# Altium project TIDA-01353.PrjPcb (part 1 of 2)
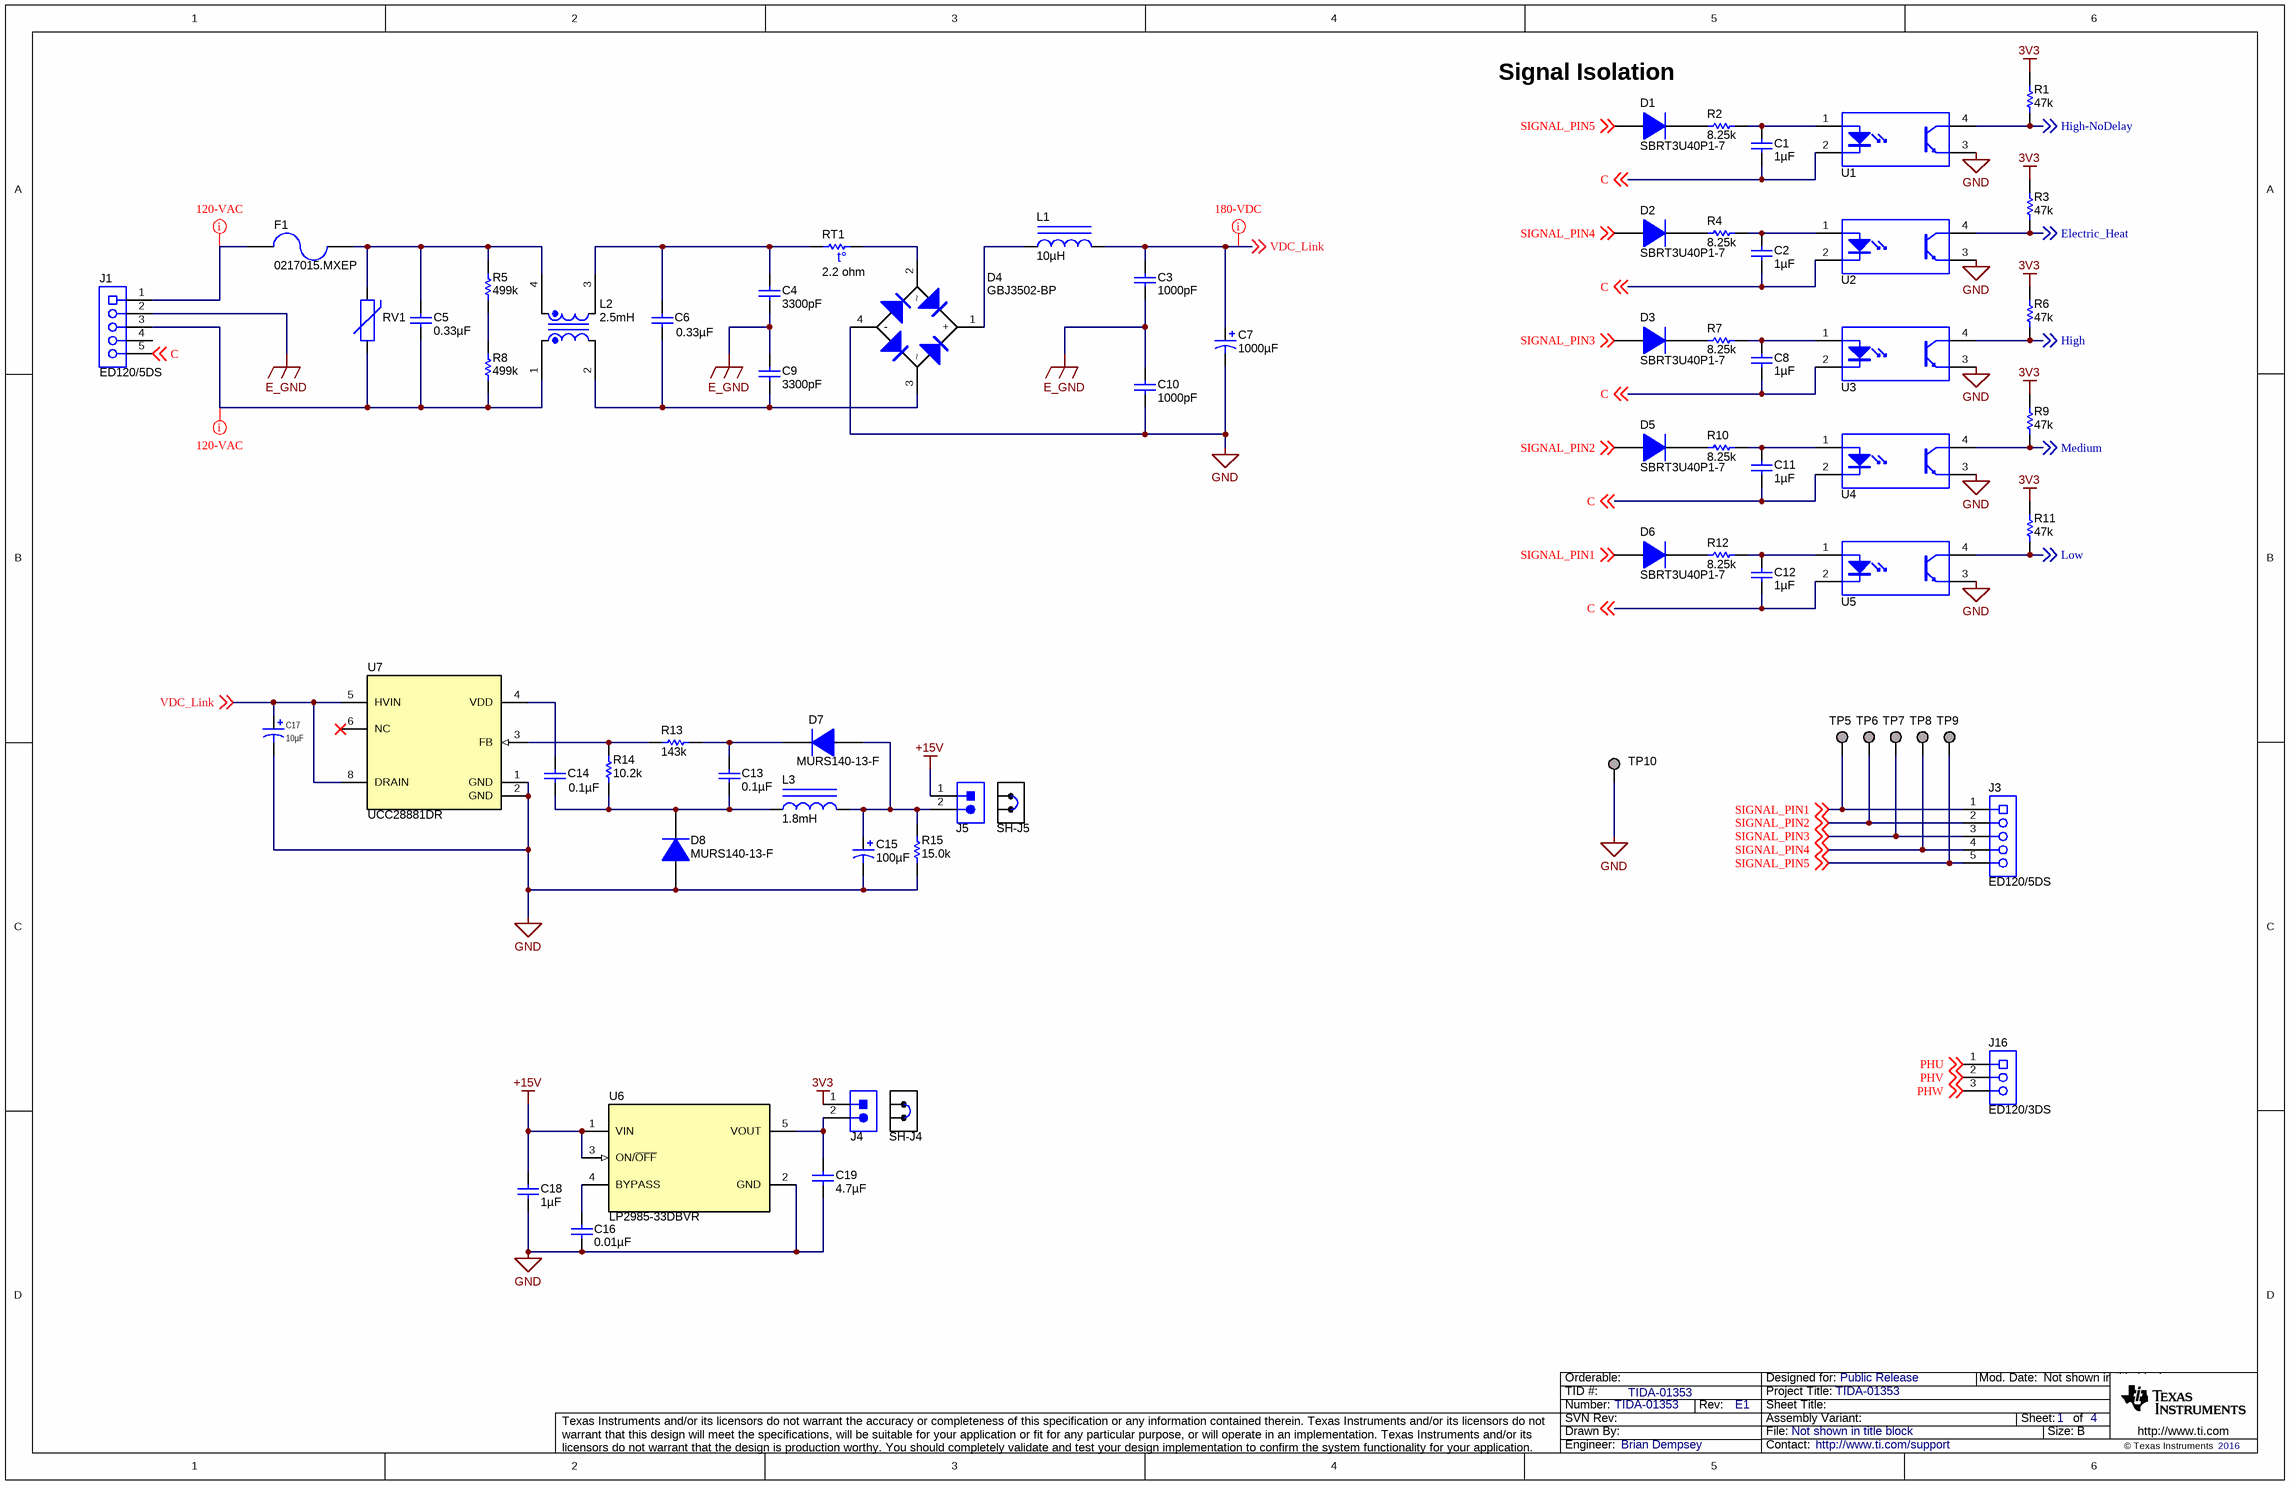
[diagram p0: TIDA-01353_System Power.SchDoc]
TID: TIDA-01353; TechSupport: http://www.ti.com/support; SCH_Rev: E1; PRJ_Title: TIDA-01353; PRJ_Number: TIDA-01353; PRJ_Engineer: Brian Dempsey; PRJ_Customer: Public Release; PCB_Rev: E1; PCB_Layout: Krypton Solutions/RS; CopyrightYear: 2016
4 sheets, 251 parts. Net scope: global (net labels, ports and power ports of the same name join across sheets).
Board file: TIDA-01353.PcbDoc
Sheets:
  TIDA-01353_System Power.SchDoc
  TIDA-01353_Motor Control.SchDoc
  TIDA-01353_MCU and Peripherals.SchDoc
  TIDA-01353_EVM_Hardware.SchDoc

## Sheet TIDA-01353_System Power.SchDoc
size 431 x 279 mm; Date: Not shown in title block; ApprovedBy: Not shown in title block; CheckedBy: Not shown in title block; Author: Not shown in title block; CompanyName: Not shown in title block; Engineer: Not shown in title block; Organization: Not shown in title block; Address1: Not shown in title block; Address2: Not shown in title block; Address3: Not shown in title block; Address4: Not shown in title block; DocumentNumber: 1; Revision: Use project parameter SCH_Rev; SheetNumber: 1; SheetTotal: 4; PageSetup: Record=PageOptions¦CenterHorizontal=True¦CenterVertical=True¦PrintScale=0.62¦XCorrection=1.00¦YCorrection=1.00¦PrintKind=0¦BorderSize=5000000¦LeftOffset=0¦BottomOffset=0¦Orientation=2¦PaperLength=1000¦PaperWidth=1000¦Scale=100¦PaperSource=15¦PrintQuality=600¦MediaType=1¦DitherType=10¦PrintScaleMode=1¦PaperKind=Letter

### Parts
C1  ValueDisplayed: 1µF  [0805_HV]  (hidden comment: 08055C105KAT2A)
C2  ValueDisplayed: 1µF  [0805_HV]  (hidden comment: 08055C105KAT2A)
C3  ValueDisplayed: 1000pF  [CAPRD750W60D750H1050]  (hidden comment: VY2102M29Y5UG63V7)
C4  ValueDisplayed: 3300pF  [KX_1000x700]  (hidden comment: DE1E3KX332MN4AP01F)
C5  ValueDisplayed: 0.33µF  [CAPRR1500W80D1750T1000H1650]  (hidden comment: BFC233840334)
C6  ValueDisplayed: 0.33µF  [CAPRR1500W80D1750T1000H1650]  (hidden comment: BFC233840334)
C7  ValueDisplayed: 1000µF  [381LR_3000x3500]  (hidden comment: 381LR102M200K032)
C8  ValueDisplayed: 1µF  [0805_HV]  (hidden comment: 08055C105KAT2A)
C9  ValueDisplayed: 3300pF  [KX_1000x700]  (hidden comment: DE1E3KX332MN4AP01F)
C10  ValueDisplayed: 1000pF  [CAPRD750W60D750H1050]  (hidden comment: VY2102M29Y5UG63V7)
C11  ValueDisplayed: 1µF  [0805_HV]  (hidden comment: 08055C105KAT2A)
C12  ValueDisplayed: 1µF  [0805_HV]  (hidden comment: 08055C105KAT2A)
C13  ValueDisplayed: 0.1µF  [0603]  (hidden comment: C0603C104K5RACTU)
C14  ValueDisplayed: 0.1µF  [0402]  (hidden comment: GRM155R61A104KA01D)
C15  ValueDisplayed: 100µF  [SM_RADIAL_D8]  (hidden comment: EEE-FK1V101XP)
C16  ValueDisplayed: 0.01µF  [0805_HV]  (hidden comment: C0805C103K5RACTU)
C17  ValueDisplayed: 10µF  [CY_1000x1600]  (hidden comment: UCY2G100MPD1TD)
C18  ValueDisplayed: 1µF  [0603]  (hidden comment: GRM188R61E105KA12D)
C19  ValueDisplayed: 4.7µF  [0603]  (hidden comment: GRM188R60J475KE19D)
D1  SBRT3U40P1-7  [PowerDI123]
D2  SBRT3U40P1-7  [PowerDI123]
D3  SBRT3U40P1-7  [PowerDI123]
D4  GBJ3502-BP  [GBJ]
D5  SBRT3U40P1-7  [PowerDI123]
D6  SBRT3U40P1-7  [PowerDI123]
D7  MURS140-13-F  [SMB]
D8  MURS140-13-F  [SMB]
F1  0217015.MXEP  [Fuse_217_015]
J1  ED120/5DS  [On-Shore_ED120_5DS]
J3  ED120/5DS  [On-Shore_ED120_5DS]
J4  HTSW-102-09-G-S  [Samtec_HTSW-102-09-x-S]  (value not drawn)
J5  HTSW-102-09-G-S  [Samtec_HTSW-102-09-x-S]  (value not drawn)
J16  ED120/3DS  [On-Shore_ED120_3DS]
L1  ValueDisplayed: 10µH  [XAL1010]  (hidden comment: XAL1010-103MEB)
L2  ValueDisplayed: 2.5mH  [8100_8109-8114]  (hidden comment: 8114-RC)
L3  ValueDisplayed: 1.8mH  [MSS1210]  (hidden comment: MSS1210-185KE)
R1  value 47k  [0603]  (hidden comment: CRCW060347K0JNEA)
R2  ValueDisplayed: 8.25k  [2512]  (hidden comment: CRCW25128K25FKEG)
R3  value 47k  [0603]  (hidden comment: CRCW060347K0JNEA)
R4  ValueDisplayed: 8.25k  [2512]  (hidden comment: CRCW25128K25FKEG)
R5  ValueDisplayed: 499k  [2010]  (hidden comment: CRCW2010499KFKEF)
R6  value 47k  [0603]  (hidden comment: CRCW060347K0JNEA)
R7  ValueDisplayed: 8.25k  [2512]  (hidden comment: CRCW25128K25FKEG)
R8  ValueDisplayed: 499k  [2010]  (hidden comment: CRCW2010499KFKEF)
R9  value 47k  [0603]  (hidden comment: CRCW060347K0JNEA)
R10  ValueDisplayed: 8.25k  [2512]  (hidden comment: CRCW25128K25FKEG)
R11  value 47k  [0603]  (hidden comment: CRCW060347K0JNEA)
R12  ValueDisplayed: 8.25k  [2512]  (hidden comment: CRCW25128K25FKEG)
R13  ValueDisplayed: 143k  [0402]  (hidden comment: CRCW0402143KFKED)
R14  ValueDisplayed: 10.2k  [0402]  (hidden comment: CRCW040210K2FKED)
R15  ValueDisplayed: 15.0k  [0402]  (hidden comment: CRCW040215K0FKED)
RT1  value 2.2 ohm  [S237]  (hidden comment: B57237S229M)
RV1  S10K275E2  [VAR_S10K275E2]  (value not drawn)
SH-J4  969102-0000-DA  [SNT-100-BK-G]  (value not drawn)
SH-J5  969102-0000-DA  [SNT-100-BK-G]  (value not drawn)
TP5  TESTPOINT  [Keystone_5019]  (value not drawn)  (no BOM)
TP6  TESTPOINT  [Keystone_5019]  (value not drawn)  (no BOM)
TP7  TESTPOINT  [Keystone_5019]  (value not drawn)  (no BOM)
TP8  TESTPOINT  [Keystone_5019]  (value not drawn)  (no BOM)
TP9  TESTPOINT  [Keystone_5019]  (value not drawn)  (no BOM)
TP10  TESTPOINT  [Keystone_5019]  (value not drawn)  (no BOM)
U1  LTV-817S  [DIP254P762X350-4]  (value not drawn)
U2  LTV-817S  [DIP254P762X350-4]  (value not drawn)
U3  LTV-817S  [DIP254P762X350-4]  (value not drawn)
U4  LTV-817S  [DIP254P762X350-4]  (value not drawn)
U5  LTV-817S  [DIP254P762X350-4]  (value not drawn)
U6  LP2985-33DBVR  [DBV0005A_N]
U7  UCC28881DR  [D0007A_N]

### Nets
3V3: J4.1 R1.2 R3.2 R6.2 R9.2 R11.2
+15V: C18.1 J5.1 U6.1(VIN) U6.3(ON/~{OFF})
E_GND: C3.2 C4.2 C9.1 C10.1 J1.2
GND: C7.2(-) C10.2 C15.2(-) C16.2 C17.2(-) C18.2 C19.2 D4.4(-) D8.2(A) R15.1 TP10.1 U1.3(E) U2.3(E) U3.3(E) U4.3(E) U5.3(E) U6.2(GND) U7.1(GND) U7.2(GND)
C: C1.2 C2.2 C8.2 C11.2 C12.2 J1.5 U1.2(K) U2.2(K) U3.2(K) U4.2(K) U5.2(K) ; off-sheet C
Electric_Heat: R3.1 U2.4(C) ; off-sheet Electric_Heat
High: R6.1 U3.4(C) ; off-sheet High
High-NoDelay: R1.1 U1.4(C) ; off-sheet High-NoDelay
Low: R11.1 U5.4(C) ; off-sheet Low
Medium: R9.1 U4.4(C) ; off-sheet Medium
PHU: J16.1 ; off-sheet PHU
PHV: J16.2 ; off-sheet PHV
PHW: J16.3 ; off-sheet PHW
SIGNAL_PIN1: D6.2(A) J3.1 TP5.1 ; off-sheet SIGNAL_PIN1
SIGNAL_PIN2: D5.2(A) J3.2 TP6.1 ; off-sheet SIGNAL_PIN2
SIGNAL_PIN3: D3.2(A) J3.3 TP7.1 ; off-sheet SIGNAL_PIN3
SIGNAL_PIN4: D2.2(A) J3.4 TP8.1 ; off-sheet SIGNAL_PIN4
SIGNAL_PIN5: D1.2(A) J3.5 TP9.1 ; off-sheet SIGNAL_PIN5
VDC_Link: C3.1 C7.1(+) C17.1(+) L1.2 U7.5(HVIN) U7.8(DRAIN) ; off-sheet VDC_Link
NetC1_1: C1.1 R2.2 U1.1(A)
NetC2_1: C2.1 R4.2 U2.1(A)
NetC4_1: C4.1 C6.1 L2.3 RT1.1
NetC5_1: C5.1 F1.1 L2.4 R5.2 RV1.2
NetC5_2: C5.2 J1.3 L2.1 R8.1 RV1.1
NetC6_2: C6.2 C9.2 D4.3 L2.2
NetC8_1: C8.1 R7.2 U3.1(A)
NetC11_1: C11.1 R10.2 U4.1(A)
NetC12_1: C12.1 R12.2 U5.1(A)
NetC13_1: C13.1 D7.1(K) R13.2
NetC13_2: C13.2 C14.2 D8.1(K) L3.1 R14.1
NetC14_1: C14.1 U7.4(VDD)
NetC15_1: C15.1(+) D7.2(A) J5.2 L3.2 R15.2
NetC16_1: C16.1 U6.4(BYPASS)
NetC19_1: C19.1 J4.2 U6.5(VOUT)
NetD1_1: D1.1(K) R2.1
NetD2_1: D2.1(K) R4.1
NetD3_1: D3.1(K) R7.1
NetD4_1: D4.1(+) L1.1
NetD4_2: D4.2 RT1.2
NetD5_1: D5.1(K) R10.1
NetD6_1: D6.1(K) R12.1
NetF1_2: F1.2 J1.1
NetR5_1: R5.1 R8.2
NetR13_1: R13.1 R14.2 U7.3(FB)

Not connected (* = marked no-connect by the designer): J1 4; U7 6(NC)*

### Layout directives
rule Undefined: NetC5_2, NetF1_2, VDC_Link

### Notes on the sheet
- Signal Isolation

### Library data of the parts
C1 C2 C8 C11 C12 = 08055C105KAT2A: CAP, CERM, 1 µF, 50 V, +/- 10%, X7R, 0805; Manufacturer: AVX; Polarized: N; CompType: Capacitor; Value: 1uF; U/M: EA; Cap_F: 0.000001; Tolerance_%: 10; Value1: Unknown; VDC_V: 50; Value2: 50V; TaMin_C: -55; TaMax_C: 125; Cap_Case: 0805; SizeArea_mm2: 2.5; SizeAreaWB_mm2: 6.75; SizeX_mm: 2; SizeY_mm: 1.25; SizeZ_mm: 1.45; AEC Category: Q200
C3 C10 = VY2102M29Y5UG63V7: CAP, CERM, 1000 pF, 300 V, +/- 20%, Y5U, Radial Disc 7.5mm, ls=7.5; Manufacturer: Vishay-Bccomponents; Polarized: N; CompType: Capacitor; Value: 1000pF; U/M: EA; Cap_F: 0.000000001; Tolerance_%: 20; Value1: Unknown; VDC_V: 300; Value2: 300V; TaMin_C: -40; TaMax_C: 125; SizeArea_mm2: 41.5; SizeAreaWB_mm2: 72.1; SizeX_mm: 8.3; SizeY_mm: 5; SizeZ_mm: 11.5; AEC Category: Q200
C4 C9 = DE1E3KX332MN4AP01F: CAP, CERM, 3300 pF, 300 V, +/- 20%, E, D10xT7mm; Manufacturer: MuRata; Polarized: N; CompType: Capacitor; Value: 3300pF; U/M: EA; Cap_F: 0.0000000033; Tolerance_%: 20; Value1: Unknown; VDC_V: 300; Value2: 300V; TaMin_C: -40; TaMax_C: 125; Cap_Case: 10x7mm; SizeArea_mm2: 70; SizeAreaWB_mm2: 108; SizeX_mm: 10; SizeY_mm: 7; SizeZ_mm: 13; AEC Category: Q200
C5 C6 = BFC233840334: CAP, Film, 0.33 µF, 630 V, +/- 20%, TH; Manufacturer: Vishay-Bccomponents; Polarized: N; CompType: Capacitor; Value: 0.33uF; U/M: EA; Cap_F: 0.00000033; Tolerance_%: 20; Value1: Unknown; VDC_V: 630; Value2: 630V; TaMin_C: -55; TaMax_C: 105; Cap_Case: 17.5x16.5x10mm; AEC Category: Q200
C7 = 381LR102M200K032: CAP, AL, 1000 µF, 200 V, +/- 20%, 0.149 ohm, TH; Manufacturer: Cornell Dubilier Electronics; Polarized: Y; CompType: Capacitor; Value: 1000uF; U/M: EA; Cap_F: 0.001; Tolerance_%: 20; VDC_V: 200; Value2: 200V; ESR_ohm: 0.149; IRMS_A: 2.84; TaMin_C: -40; TaMax_C: 105; Cap_Case: 30x35mm; SizeAreaWB_mm2: 1024; SizeArea_mm2: 900; SizeX_mm: 30; SizeZ_mm: 37; AEC Category: Q200; AEC Qualified: N
C13 = C0603C104K5RACTU: CAP, CERM, 0.1 µF, 50 V, +/- 10%, X7R, 0603; Manufacturer: Kemet; Polarized: N; CompType: Capacitor; Value: 0.1uF; U/M: EA; Cap_F: 0.0000001; Tolerance_%: 10; Value1: Unknown; VDC_V: 50; Value2: 50V; TaMin_C: -55; TaMax_C: 125; SizeArea_mm2: 1.28; SizeAreaWB_mm2: 4.68; SizeX_mm: 1.6; SizeY_mm: 0.8; SizeZ_mm: 1; AEC Category: Q200
C14 = GRM155R61A104KA01D: CAP, CERM, 0.1 µF, 10 V, +/- 10%, X5R, 0402; Manufacturer: MuRata; Polarized: N; CompType: Capacitor; Value: 0.1uF; U/M: EA; Cap_F: 0.0000001; Tolerance_%: 10; Value1: Unknown; Value2: 10V; TaMin_C: -55; TaMax_C: 85; SizeArea_mm2: 0.5; SizeAreaWB_mm2: 3; SizeX_mm: 1; SizeZ_mm: 0.6; AEC Category: Q200
C15 = EEE-FK1V101XP: CAP, AL, 100 µF, 35 V, +/- 20%, 0.34 ohm, AEC-Q200 Grade 2, SMD; Manufacturer: Panasonic; Polarized: Y; CompType: Capacitor; Value: 100uF; U/M: EA; Cap_F: 0.0001; Tolerance_%: 20; VDC_V: 35; Value2: 35V; ESR_ohm: 0.34; IRMS_A: 0.28; TaMin_C: -55; TaMax_C: 105; Cap_Case: D8; SizeAreaWB_mm2: 84.28; SizeArea_mm2: 51.48; SizeX_mm: 7.8; SizeY_mm: 6.6; SizeZ_mm: 7.7; AEC Category: Q200; AEC Grade: 2
C16 = C0805C103K5RACTU: CAP, CERM, 0.01 µF, 50 V, +/- 10%, X7R, 0805; Manufacturer: Kemet; Polarized: N; CompType: Capacitor; Value: 0.01uF; U/M: EA; Cap_F: 0.00000001; Tolerance_%: 10; ESR_ohm: 1.739; Value1: 1.739 ohm; VDC_V: 50; Value2: 50V; IRMS_A: 0.411; TaMin_C: -55; TaMax_C: 125; Cap_Case: 0805; SizeArea_mm2: 2.5; SizeAreaWB_mm2: 6.75; SizeX_mm: 2; SizeY_mm: 1.25; SizeZ_mm: 1.45; AEC Category: Q200
C17 = UCY2G100MPD1TD: CAP, AL, 10 µF, 400 V, +/- 20%,  ohm, TH; Manufacturer: Nichicon; Polarized: Y; CompType: Capacitor; Value: 10uF; U/M: EA; Cap_F: 0.00001; Tolerance_%: 20; Value1: Unknown; VDC_V: 400; Value2: 400V; IRMS_A: 0.15; TaMin_C: -40; TaMax_C: 105; Cap_Case: 10x16mm
C18 = GRM188R61E105KA12D: CAP, CERM, 1 µF, 25 V, +/- 10%, X5R, 0603; Manufacturer: MuRata; Polarized: N; CompType: Capacitor; Value: 1uF; U/M: EA; Cap_F: 0.000001; Tolerance_%: 10; Value1: Unknown; VDC_V: 25; Value2: 25V; TaMin_C: -55; TaMax_C: 85; SizeArea_mm2: 1.28; SizeAreaWB_mm2: 4.68; SizeX_mm: 1.6; SizeY_mm: 0.8; SizeZ_mm: 1; AEC Category: Q200
C19 = GRM188R60J475KE19D: CAP, CERM, 4.7 µF, 6.3 V, +/- 10%, X5R, 0603; Manufacturer: MuRata; Polarized: N; CompType: Capacitor; Value: 4.7uF; U/M: EA; Cap_F: 0.0000047; Tolerance_%: 10; ESR_ohm: 0.005; Value1: 0.005 ohm; VDC_V: 6.3; Value2: 6.3V; IRMS_A: 2; TaMin_C: -55; TaMax_C: 85; SizeArea_mm2: 1.28; SizeAreaWB_mm2: 4.68; SizeX_mm: 1.6; SizeY_mm: 0.8; SizeZ_mm: 1; AEC Category: Q200
D1-D3 D5 D6 = SBRT3U40P1-7: Diode, Super Barrier Rectifier, 40 V, 3 A, AEC-Q101, PowerDI123; Manufacturer: Diodes Inc.; U/M: EA; Vf_V: 0.49; Value: 40V; Value1: 3A; Value2: 0.49V; Io_A: 3; Vr_V: 40; TJmax_C: 150; RJC_CperW: 19; SizeAreaWB_mm2: 13.066; SizeArea_mm2: 6.586; SizeX_mm: 3.7; SizeY_mm: 1.78; SizeZ_mm: 0.98; AEC Category: Q101; AEC Qualified: Y
D4 = GBJ3502-BP: Diode, P-N-Bridge, 200 V, 35 A, TH; Manufacturer: Micro Commercial Components; U/M: EA; Vf_V: 1.05; Value: 200V; Value1: 35A; Value2: 1.05V; Io_A: 35; Vr_V: 200; TJmax_C: 150; RJC_CperW: 0.6; SizeAreaWB_mm2: 211.2; SizeArea_mm2: 138; SizeX_mm: 30; SizeY_mm: 4.6; SizeZ_mm: 24; AEC Category: Q101
D7 D8 = MURS140-13-F: Diode, Ultrafast, 400 V, 1 A, SMB; Manufacturer: Diodes Inc.; U/M: EA; Vf_V: 1.25; Value: 400V; Value1: 1A; Value2: 1.25V; Io_A: 1; Vr_V: 400; TJmax_C: 150; RJC_CperW: 13; SizeAreaWB_mm2: 44.156; SizeArea_mm2: 21.336; SizeX_mm: 5.6; SizeY_mm: 3.81; SizeZ_mm: 2.6; AEC Category: Q101
F1 = 0217015.MXEP: Fuse, 15 A, 250 VDC, TH; Manufacturer: Littelfuse; VDC_V: 250; Irating_A: 15; Rtyp_Ohm: 0.04; MeltingTyp: 617.135
J1 J3 = ED120/5DS: Terminal Block, 5.08 mm, 5x1, Brass, TH; Manufacturer: On-Shore Technology; SymbolCreator: a0412235; Pitch_mm: 5.08; Gender: Female; Shrouded: N; Row_Count: 1; Current_A: 15; Voltage_V: 300; Cert_CULUS: Y
J4 J5 = HTSW-102-09-G-S: Header, 100mil, 2x1, Gold, TH; Manufacturer: Samtec; SymbolCreator: a0412235; Pitch_mm: 2.54; Gender: Male; Row_Count: 1; Cert_CSA: Y
J16 = ED120/3DS: Terminal Block, 5.08 mm, 3x1, Brass, TH; Manufacturer: On-Shore Technology; SymbolCreator: a0412235; Pitch_mm: 5.08; Gender: Female; Shrouded: N; Row_Count: 1; Current_A: 15; Voltage_V: 300; Cert_CULUS: Y
L1 = XAL1010-103MEB: Inductor, Shielded, Composite, 10 µH, 15.5 A, 0.01 ohm, SMD; Manufacturer: Coilcraft; Value: 10uH; Ind_H: 10.0E-6; Imax_A: 15.5; Irms: 15.5A @ 40C rise; Isat: 17.5A @ 30% inductance drop; DCR_ohm: 0.01; Value2: 15.5A; SizeAreaWB_mm2: 159.6; SizeArea_mm2: 113; SizeX_mm: 11.3; SizeY_mm: 10; AEC Category: Q200
L2 = 8114-RC: Coupled inductor, 2.5 mH, 12.5 A, 0.011 ohm, TH; Manufacturer: Bourns; SymbolCreator: a0412235; Value: 2.5mH; Ind_H: 2.5E-3; DCR_ohm: 0.011
L3 = MSS1210-185KE: Inductor, Shielded, Ferrite, 1.8 mH, 0.79 A, 1.54 ohm, SMD; Manufacturer: Coilcraft; Value: 1.8mH; Ind_H: 1.8E-3; Imax_A: 0.79; Irms: 0.79A @ 40C rise; Isat: 0.95A @ 30% inductance drop; DCR_ohm: 1.54; Value2: 0.79A; SizeAreaWB_mm2: 204.49; SizeArea_mm2: 151.29; SizeX_mm: 12.3; SizeZ_mm: 10; AEC Category: Q200
R1 R3 R6 R9 R11 = CRCW060347K0JNEA: RES, 47k ohm, 5%, 0.1W, 0603; Manufacturer: Vishay-Dale; CompType: Resistor; Res_ohm: 47000; Value_Code: 47k0; Tolerance_%: 5; Power_W: 0.1; VDC_V: 75; TempCo: 200 ppm/C; EIA_Code: E24; U/M: EA
R2 R4 R7 R10 R12 = CRCW25128K25FKEG: RES, 8.25 k, 1%, 1 W, AEC-Q200 Grade 0, 2512; Manufacturer: Vishay-Dale; CompType: Resistor; Value: 8.25k; Res_ohm: 8250; Value_Code: 8k25; Tolerance_%: 1; Value2: 1W; VDC_V: 500; TempCo: 100 ppm/C; SizeArea_mm2: 20.16; SizeX_mm: 6.3; SizeY_mm: 3.2; SizeZ_mm: 0.71; EIA_Code: E96; U/M: EA; AEC Category: Q200; AEC Qualified: Y; AEC Grade: 0
R5 R8 = CRCW2010499KFKEF: RES, 499 k, 1%, 0.75 W, AEC-Q200 Grade 0, 2010; Manufacturer: Vishay-Dale; CompType: Resistor; Value: 499k; Res_ohm: 499000; Tolerance_%: 1; Power_W: 0.75; Value2: 0.75W; VDC_V: 400; TempCo: 100 ppm/C; SizeArea_mm2: 12.5; SizeX_mm: 5; SizeY_mm: 2.5; SizeZ_mm: 1.66; EIA_Code: E96; U/M: EA; AEC Category: Q200; AEC Qualified: Y; AEC Grade: 0
R13 = CRCW0402143KFKED: RES, 143 k, 1%, 0.063 W, 0402; Manufacturer: Vishay-Dale; CompType: Resistor; Value: 143k; Res_ohm: 143000; Tolerance_%: 1; Power_W: 0.063; Value2: 0.063W; VDC_V: 50; TempCo: 100 ppm/C; SizeArea_mm2: 0.5; SizeZ_mm: 0.6; EIA_Code: E96; U/M: EA; AEC Category: Q200
R14 = CRCW040210K2FKED: RES, 10.2 k, 1%, 0.063 W, 0402; Manufacturer: Vishay-Dale; CompType: Resistor; Value: 10.2k; Res_ohm: 10200; Value_Code: 10k2; Tolerance_%: 1; Power_W: 0.063; Value2: 0.063W; VDC_V: 50; TempCo: 100 ppm/C; SizeArea_mm2: 0.5; SizeZ_mm: 0.6; EIA_Code: E96; U/M: EA; AEC Category: Q200
R15 = CRCW040215K0FKED: RES, 15.0 k, 1%, 0.063 W, 0402; Manufacturer: Vishay-Dale; CompType: Resistor; Value: 15.0k; Res_ohm: 15000; Value_Code: 15k0; Tolerance_%: 1; Power_W: 0.063; Value2: 0.063W; VDC_V: 50; TempCo: 100 ppm/C; SizeArea_mm2: 0.5; SizeZ_mm: 0.6; EIA_Code: E96; U/M: EA; AEC Category: Q200
RT1 = B57237S229M: Thermistor NTC, 2.2 ohm, 20%, 15x7mm; Manufacturer: TDK; Tolerance_%: 20; Power_W: 3.1; TaMin_C: -55; TaMax_C: 170; U/M: EA
RV1 = S10K275E2: Varistor 275V RMS 10MM Radial, TH; Manufacturer: TDK; SymbolCreator: a0412235
SH-J4 SH-J5 = 969102-0000-DA: Shunt, 100mil, Gold plated, Black; Manufacturer: 3M; Alternate Manufacturer: Samtec; Value: 1x2; Note: You can "mate" this to a header by matching the designator.  i.e. use SH-J3 for header J3
TP5-TP10 = 5019: Test Point, Miniature, SMT; Manufacturer: Keystone; CompType: Test Point Loop
U1-U5 = LTV-817S: Optocoupler, 5 kV, 50-600% CTR, SMT; Manufacturer: Lite-On; CTR (Min): 50%; CTR (Max): 600%; Voltage_Isolation_Vrms: 5000V; SizeAreaWB_mm2: 80.256; SizeArea_mm2: 46.736; SizeX_mm: 10.16; SizeY_mm: 4.6
U6 = LP2985-33DBVR: 100-mA ULTRA-LOW DROPOUT REGULATOR WITH SHUTDOWN, DBV0005A (SOT-5); Alternate PartNumber: LP2985-33DBVT; Manufacturer: Texas Instruments; SymbolCreator: Altium; SizeArea_mm2: 8.12; SizeAreaWB_mm2: 14.82; SizeX_mm: 2.8; SizeY_mm: 2.9; SizeZ_mm: 1.45; CompType: IC; U/M: EA
U7 = UCC28881DR: 700-V Lowest Quiescent Current Off-Line Switcher, D0007A (SOIC-7); Manufacturer: Texas Instruments; SymbolCreator: a0411947; SizeArea_mm2: 29.4; SizeAreaWB_mm2: 55.2; SizeX_mm: 6; SizeY_mm: 4.9; SizeZ_mm: 1.75; CompType: IC; U/M: EA

## Sheet TIDA-01353_Motor Control.SchDoc
size 431 x 279 mm; Date: Not shown in title block; ApprovedBy: Not shown in title block; CheckedBy: Not shown in title block; Author: Not shown in title block; CompanyName: Not shown in title block; Engineer: Not shown in title block; Organization: Not shown in title block; Address1: Not shown in title block; Address2: Not shown in title block; Address3: Not shown in title block; Address4: Not shown in title block; DocumentNumber: 1; Revision: Use project parameter SCH_Rev; SheetNumber: 2; SheetTotal: 4; PageSetup: Record=PageOptions¦CenterHorizontal=True¦CenterVertical=True¦PrintScale=1.00¦XCorrection=1.00¦YCorrection=1.00¦PrintKind=0¦BorderSize=5000000¦LeftOffset=0¦BottomOffset=0¦Orientation=2¦PaperLength=1000¦PaperWidth=1000¦Scale=100¦PaperSource=15¦PrintQuality=600¦MediaType=1¦DitherType=10¦PaperKind=Letter¦PrintScaleMode=1
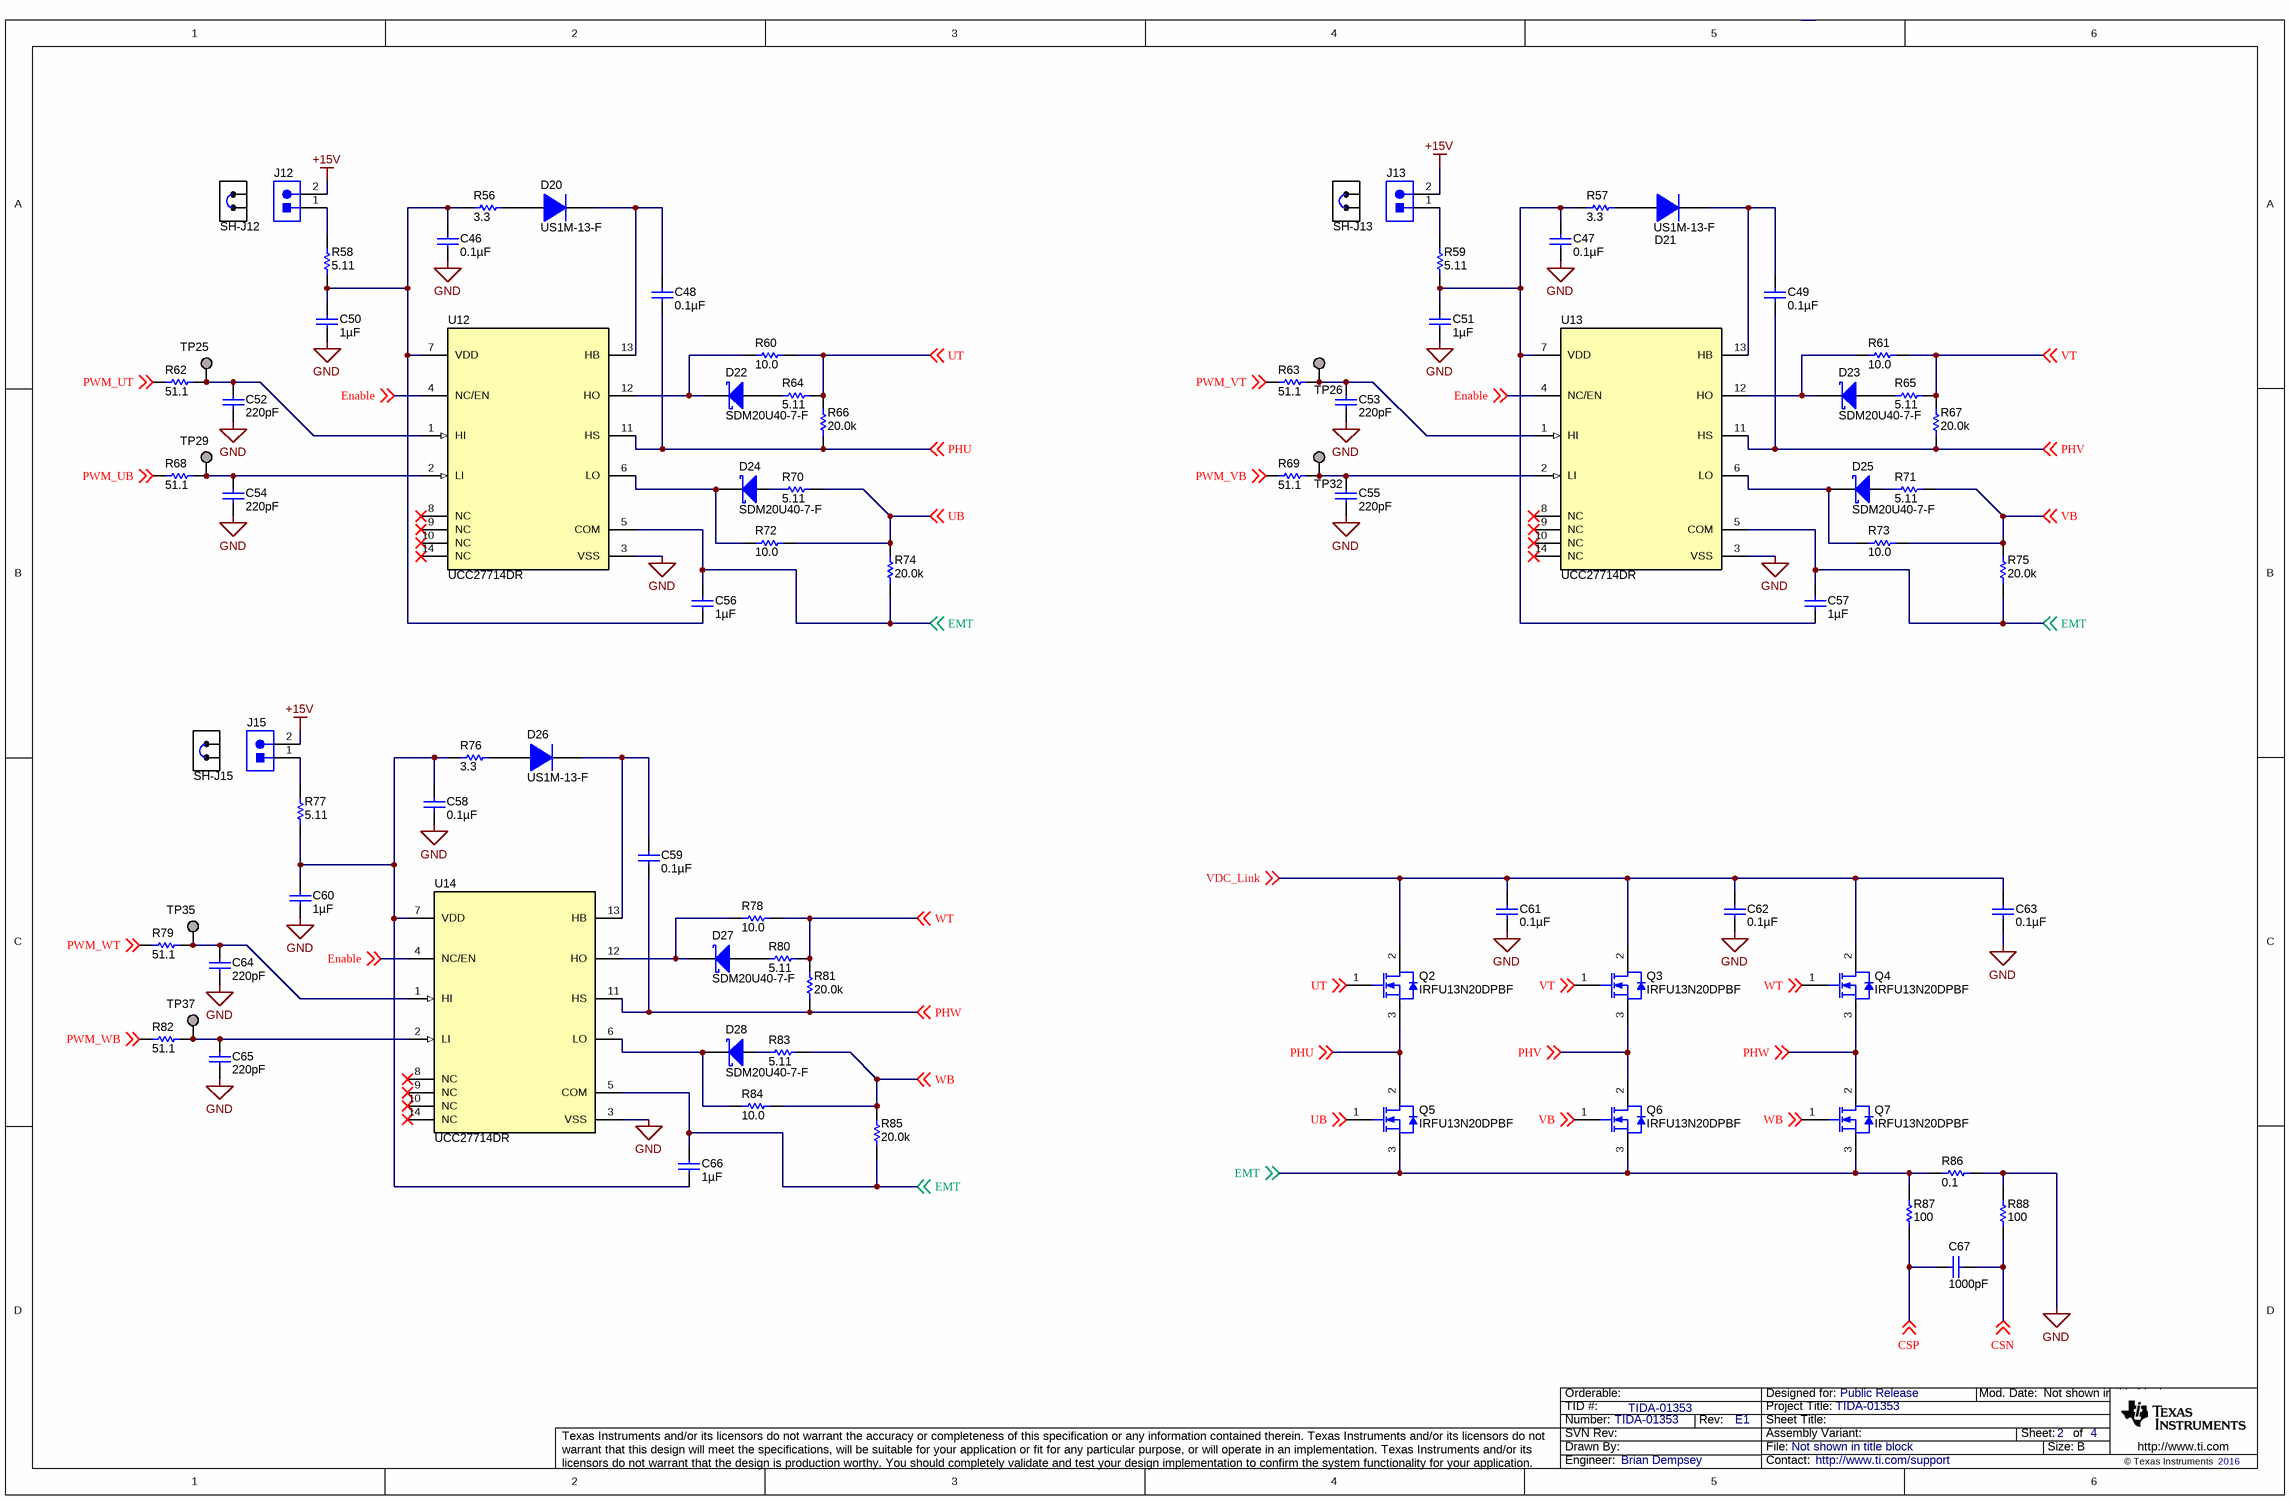
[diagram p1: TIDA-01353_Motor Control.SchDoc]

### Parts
C46  ValueDisplayed: 0.1µF  [0603S]  (hidden comment: 06033C104JAT2A)
C47  ValueDisplayed: 0.1µF  [0603S]  (hidden comment: 06033C104JAT2A)
C48  ValueDisplayed: 0.1µF  [0805_HV1]  (hidden comment: GRM21BR71E104KA01L)
C49  ValueDisplayed: 0.1µF  [0805_HV1]  (hidden comment: GRM21BR71E104KA01L)
C50  ValueDisplayed: 1µF  [0805_HV]  (hidden comment: GRM21BR71E105KA99L)
C51  ValueDisplayed: 1µF  [0805_HV]  (hidden comment: GRM21BR71E105KA99L)
C52  ValueDisplayed: 220pF  [0603]  (hidden comment: 06035A221FAT2A)
C53  ValueDisplayed: 220pF  [0603]  (hidden comment: 06035A221FAT2A)
C54  ValueDisplayed: 220pF  [0603]  (hidden comment: 06035A221FAT2A)
C55  ValueDisplayed: 220pF  [0603]  (hidden comment: 06035A221FAT2A)
C56  ValueDisplayed: 1µF  [0805_HV]  (hidden comment: GRM21BR71E105KA99L)
C57  ValueDisplayed: 1µF  [0805_HV]  (hidden comment: GRM21BR71E105KA99L)
C58  ValueDisplayed: 0.1µF  [0603S]  (hidden comment: 06033C104JAT2A)
C59  ValueDisplayed: 0.1µF  [0805_HV1]  (hidden comment: GRM21BR71E104KA01L)
C60  ValueDisplayed: 1µF  [0805_HV]  (hidden comment: GRM21BR71E105KA99L)
C61  ValueDisplayed: 0.1µF  [1808]  (hidden comment: VJ1808Y104KXPAT5Z)
C62  ValueDisplayed: 0.1µF  [1808]  (hidden comment: VJ1808Y104KXPAT5Z)
C63  ValueDisplayed: 0.1µF  [1808]  (hidden comment: VJ1808Y104KXPAT5Z)
C64  ValueDisplayed: 220pF  [0603]  (hidden comment: 06035A221FAT2A)
C65  ValueDisplayed: 220pF  [0603]  (hidden comment: 06035A221FAT2A)
C66  ValueDisplayed: 1µF  [0805_HV]  (hidden comment: GRM21BR71E105KA99L)
C67  ValueDisplayed: 1000pF  [0603]  (hidden comment: GRM188R61H102KA01D)
D20  US1M-13-F  [SMA]
D21  US1M-13-F  [SMA]
D22  SDM20U40-7-F  [SOD-523]
D23  SDM20U40-7-F  [SOD-523]
D24  SDM20U40-7-F  [SOD-523]
D25  SDM20U40-7-F  [SOD-523]
D26  US1M-13-F  [SMA]
D27  SDM20U40-7-F  [SOD-523]
D28  SDM20U40-7-F  [SOD-523]
J12  HTSW-102-09-G-S  [Samtec_HTSW-102-09-x-S]  (value not drawn)
J13  HTSW-102-09-G-S  [Samtec_HTSW-102-09-x-S]  (value not drawn)
J15  HTSW-102-09-G-S  [Samtec_HTSW-102-09-x-S]  (value not drawn)
Q2  IRFU13N20DPBF  [IPAK]
Q3  IRFU13N20DPBF  [IPAK]
Q4  IRFU13N20DPBF  [IPAK]
Q5  IRFU13N20DPBF  [IPAK]
Q6  IRFU13N20DPBF  [IPAK]
Q7  IRFU13N20DPBF  [IPAK]
R56  ValueDisplayed: 3.3  [0603]  (hidden comment: CRCW06033R30JNEA)
R57  ValueDisplayed: 3.3  [0603]  (hidden comment: CRCW06033R30JNEA)
R58  ValueDisplayed: 5.11  [0603]  (hidden comment: RC0603FR-075R11L)
R59  ValueDisplayed: 5.11  [0603]  (hidden comment: RC0603FR-075R11L)
R60  ValueDisplayed: 10.0  [0603]  (hidden comment: CRCW060310R0FKEAHP)
R61  ValueDisplayed: 10.0  [0603]  (hidden comment: CRCW060310R0FKEAHP)
R62  ValueDisplayed: 51.1  [0603]  (hidden comment: CRCW060351R1FKEA)
R63  ValueDisplayed: 51.1  [0603]  (hidden comment: CRCW060351R1FKEA)
R64  ValueDisplayed: 5.11  [0603]  (hidden comment: RC0603FR-075R11L)
R65  ValueDisplayed: 5.11  [0603]  (hidden comment: RC0603FR-075R11L)
R66  ValueDisplayed: 20.0k  [0603]  (hidden comment: CRCW060320K0FKEA)
R67  ValueDisplayed: 20.0k  [0603]  (hidden comment: CRCW060320K0FKEA)
R68  ValueDisplayed: 51.1  [0603]  (hidden comment: CRCW060351R1FKEA)
R69  ValueDisplayed: 51.1  [0603]  (hidden comment: CRCW060351R1FKEA)
R70  ValueDisplayed: 5.11  [0603]  (hidden comment: RC0603FR-075R11L)
R71  ValueDisplayed: 5.11  [0603]  (hidden comment: RC0603FR-075R11L)
R72  ValueDisplayed: 10.0  [0603]  (hidden comment: CRCW060310R0FKEAHP)
R73  ValueDisplayed: 10.0  [0603]  (hidden comment: CRCW060310R0FKEAHP)
R74  ValueDisplayed: 20.0k  [0603]  (hidden comment: CRCW060320K0FKEA)
R75  ValueDisplayed: 20.0k  [0603]  (hidden comment: CRCW060320K0FKEA)
R76  ValueDisplayed: 3.3  [0603]  (hidden comment: CRCW06033R30JNEA)
R77  ValueDisplayed: 5.11  [0603]  (hidden comment: RC0603FR-075R11L)
R78  ValueDisplayed: 10.0  [0603]  (hidden comment: CRCW060310R0FKEAHP)
R79  ValueDisplayed: 51.1  [0603]  (hidden comment: CRCW060351R1FKEA)
R80  ValueDisplayed: 5.11  [0603]  (hidden comment: RC0603FR-075R11L)
R81  ValueDisplayed: 20.0k  [0603]  (hidden comment: CRCW060320K0FKEA)
R82  ValueDisplayed: 51.1  [0603]  (hidden comment: CRCW060351R1FKEA)
R83  ValueDisplayed: 5.11  [0603]  (hidden comment: RC0603FR-075R11L)
R84  ValueDisplayed: 10.0  [0603]  (hidden comment: CRCW060310R0FKEAHP)
R85  ValueDisplayed: 20.0k  [0603]  (hidden comment: CRCW060320K0FKEA)
R86  ValueDisplayed: 0.1  [TO-220AC]  (hidden comment: PWR220T-20-R100F)
R87  ValueDisplayed: 100  [0603]  (hidden comment: CRCW0603100RFKEA)
R88  ValueDisplayed: 100  [0603]  (hidden comment: CRCW0603100RFKEA)
SH-J12  969102-0000-DA  [SNT-100-BK-G]  (value not drawn)
SH-J13  969102-0000-DA  [SNT-100-BK-G]  (value not drawn)
SH-J15  969102-0000-DA  [SNT-100-BK-G]  (value not drawn)
TP25  TESTPOINT  [Keystone_5019]  (value not drawn)  (no BOM)
TP26  TESTPOINT  [Keystone_5019]  (value not drawn)  (no BOM)
TP29  TESTPOINT  [Keystone_5019]  (value not drawn)  (no BOM)
TP32  TESTPOINT  [Keystone_5019]  (value not drawn)  (no BOM)
TP35  TESTPOINT  [Keystone_5019]  (value not drawn)  (no BOM)
TP37  TESTPOINT  [Keystone_5019]  (value not drawn)  (no BOM)
U12  UCC27714DR  [D0014A_N]
U13  UCC27714DR  [D0014A_N]
U14  UCC27714DR  [D0014A_N]

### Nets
+15V: J12.2 J13.2 J15.2
GND: C46.2 C47.2 C50.2 C51.2 C52.2 C53.2 C54.2 C55.2 C58.2 C60.2 C61.2 C62.2 C63.2 C64.2 C65.2 R86.3 R88.2 U12.3(VSS) U13.3(VSS) U14.3(VSS)
CSN: C67.2 R88.1 ; off-sheet CSN
CSP: C67.1 R87.1 ; off-sheet CSP
EMT: C56.1 C57.1 C66.1 Q5.3(S) Q6.3(S) Q7.3(S) R74.1 R75.1 R85.1 R86.1 R87.2 U12.5(COM) U13.5(COM) U14.5(COM) ; off-sheet EMT
Enable: U12.4(NC/EN) U13.4(NC/EN) U14.4(NC/EN) ; off-sheet Enable
PHU: C48.2 Q2.3(S) Q5.2(D) R66.1 U12.11(HS) ; off-sheet PHU
PHV: C49.2 Q3.3(S) Q6.2(D) R67.1 U13.11(HS) ; off-sheet PHV
PHW: C59.2 Q4.3(S) Q7.2(D) R81.1 U14.11(HS) ; off-sheet PHW
PWM_UB: R68.1 ; off-sheet PWM_UB
PWM_UT: R62.1 ; off-sheet PWM_UT
PWM_VB: R69.1 ; off-sheet PWM_VB
PWM_VT: R63.1 ; off-sheet PWM_VT
PWM_WB: R82.1 ; off-sheet PWM_WB
PWM_WT: R79.1 ; off-sheet PWM_WT
UB: Q5.1(G) R70.2 R72.2 R74.2 ; off-sheet UB
UT: Q2.1(G) R60.2 R64.2 R66.2 ; off-sheet UT
VB: Q6.1(G) R71.2 R73.2 R75.2 ; off-sheet VB
VDC_Link: C61.1 C62.1 C63.1 Q2.2(D) Q3.2(D) Q4.2(D) ; off-sheet VDC_Link
VT: Q3.1(G) R61.2 R65.2 R67.2 ; off-sheet VT
WB: Q7.1(G) R83.2 R84.2 R85.2 ; off-sheet WB
WT: Q4.1(G) R78.2 R80.2 R81.2 ; off-sheet WT
NetC46_1: C46.1 C50.1 C56.2 R56.1 R58.1 U12.7(VDD)
NetC47_1: C47.1 C51.1 C57.2 R57.1 R59.1 U13.7(VDD)
NetC48_1: C48.1 D20.1(K) U12.13(HB)
NetC49_1: C49.1 D21.1(K) U13.13(HB)
NetC52_1: C52.1 R62.2 TP25.1 U12.1(HI)
NetC53_1: C53.1 R63.2 TP26.1 U13.1(HI)
NetC54_1: C54.1 R68.2 TP29.1 U12.2(LI)
NetC55_1: C55.1 R69.2 TP32.1 U13.2(LI)
NetC58_1: C58.1 C60.1 C66.2 R76.1 R77.1 U14.7(VDD)
NetC59_1: C59.1 D26.1(K) U14.13(HB)
NetC64_1: C64.1 R79.2 TP35.1 U14.1(HI)
NetC65_1: C65.1 R82.2 TP37.1 U14.2(LI)
NetD20_2: D20.2(A) R56.2
NetD21_2: D21.2(A) R57.2
NetD22_1: D22.1(K) R60.1 U12.12(HO)
NetD22_2: D22.2(A) R64.1
NetD23_1: D23.1(K) R61.1 U13.12(HO)
NetD23_2: D23.2(A) R65.1
NetD24_1: D24.1(K) R72.1 U12.6(LO)
NetD24_2: D24.2(A) R70.1
NetD25_1: D25.1(K) R73.1 U13.6(LO)
NetD25_2: D25.2(A) R71.1
NetD26_2: D26.2(A) R76.2
NetD27_1: D27.1(K) R78.1 U14.12(HO)
NetD27_2: D27.2(A) R80.1
NetD28_1: D28.1(K) R84.1 U14.6(LO)
NetD28_2: D28.2(A) R83.1
NetJ12_1: J12.1 R58.2
NetJ13_1: J13.1 R59.2
NetJ15_1: J15.1 R77.2

Not connected (* = marked no-connect by the designer): U12 8(NC)* 9(NC)* 10(NC)* 14(NC)*; U13 8(NC)* 9(NC)* 10(NC)* 14(NC)*; U14 8(NC)* 9(NC)* 10(NC)* 14(NC)*

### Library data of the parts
C46 C47 C58 = 06033C104JAT2A: CAP, CERM, 0.1 µF, 25 V, +/- 5%, X7R, 0603; Manufacturer: AVX; Polarized: N; CompType: Capacitor; Value: 0.1uF; U/M: EA; Cap_F: 0.0000001; Tolerance_%: 5; ESR_ohm: 0.05; Value1: 0.05 ohm; VDC_V: 25; Value2: 25V; TaMin_C: -55; TaMax_C: 125; Cap_Case: 0603; SizeArea_mm2: 1.28; SizeAreaWB_mm2: 4.68; SizeX_mm: 1.6; SizeY_mm: 0.8; SizeZ_mm: 1; AEC Category: Q200
C48 C49 C59 = GRM21BR71E104KA01L: CAP, CERM, 0.1 µF, 25 V, +/- 10%, X7R, 0805; Manufacturer: MuRata; Polarized: N; CompType: Capacitor; Value: 0.1uF; U/M: EA; Cap_F: 0.0000001; Tolerance_%: 10; Value1: Unknown; VDC_V: 25; Value2: 25V; TaMin_C: -55; TaMax_C: 125; Cap_Case: 0805; SizeArea_mm2: 2.5; SizeAreaWB_mm2: 6.75; SizeX_mm: 2; SizeY_mm: 1.25; SizeZ_mm: 1.45; AEC Category: Q200
C50 C51 C56 C57 C60 C66 = GRM21BR71E105KA99L: CAP, CERM, 1 µF, 25 V, +/- 10%, X7R, 0805; Manufacturer: MuRata; Polarized: N; CompType: Capacitor; Value: 1uF; U/M: EA; Cap_F: 0.000001; Tolerance_%: 10; Value1: Unknown; VDC_V: 25; Value2: 25V; TaMin_C: -55; TaMax_C: 125; Cap_Case: 0805; SizeArea_mm2: 2.5; SizeAreaWB_mm2: 6.75; SizeX_mm: 2; SizeY_mm: 1.25; SizeZ_mm: 1.45; AEC Category: Q200
C52-C55 C64 C65 = 06035A221FAT2A: CAP, CERM, 220 pF, 50 V, +/- 1%, C0G/NP0, 0603; Manufacturer: AVX; Polarized: N; CompType: Capacitor; Value: 220pF; U/M: EA; Cap_F: 0.00000000022; Tolerance_%: 1; ESR_ohm: 0.083; Value1: 0.083 ohm; VDC_V: 50; Value2: 50V; TaMin_C: -55; TaMax_C: 125; SizeArea_mm2: 1.28; SizeAreaWB_mm2: 4.68; SizeX_mm: 1.6; SizeY_mm: 0.8; AEC Category: Q200
C61-C63 = VJ1808Y104KXPAT5Z: CAP, CERM, 0.1 µF, 250 V, +/- 10%, X7R, 1808; Manufacturer: Vishay-Vitramon; Polarized: N; CompType: Capacitor; Value: 0.1uF; U/M: EA; Cap_F: 0.0000001; Tolerance_%: 10; Value1: Unknown; VDC_V: 250; Value2: 250V; TaMin_C: -55; TaMax_C: 125; SizeArea_mm2: 9; SizeAreaWB_mm2: 16.5; SizeX_mm: 4.5; SizeY_mm: 2; SizeZ_mm: 2.03; AEC Category: Q200
C67 = GRM188R61H102KA01D: CAP, CERM, 1000 pF, 50 V, +/- 10%, X5R, 0603; Manufacturer: MuRata; Polarized: N; CompType: Capacitor; Value: 1000pF; U/M: EA; Cap_F: 0.000000001; Tolerance_%: 10; Value1: Unknown; VDC_V: 50; Value2: 50V; TaMin_C: -55; TaMax_C: 85
D20 D21 D26 = US1M-13-F: Diode, Ultrafast, 1000 V, 1 A, SMA; Manufacturer: Diodes Inc.; U/M: EA; Vf_V: 1.7; Value: 1000V; Value1: 1A; Value2: 1.7V; Io_A: 1; Vr_V: 1000; TJmax_C: 150; RJC_CperW: 30; SizeAreaWB_mm2: 37.3428; SizeArea_mm2: 16.3228; SizeX_mm: 5.59; SizeY_mm: 2.92; SizeZ_mm: 2.87; AEC Category: Q101
D22-D25 D27 D28 = SDM20U40-7-F: Diode, Schottky, 40 V, 0.25 A, SOD-523; Manufacturer: Diodes Inc.; U/M: EA; Vf_V: 0.55; Value: 40V; Value1: 0.25A; Value2: 0.55V; Io_A: 0.25; Vr_V: 40; SizeAreaWB_mm2: 5.13; SizeArea_mm2: 1.53; SizeX_mm: 1.7; SizeY_mm: 0.9; SizeZ_mm: 0.65; AEC Category: Q101
J12 J13 J15 = HTSW-102-09-G-S: as J4 on sheet TIDA-01353_System Power
Q2-Q7 = IRFU13N20DPBF: MOSFET, N-CH, 200 V, 13 A, IPAK; Manufacturer: International Rectifier; Alternate Manufacturer: None; U/M: EA; ChType: N; Value: 200V; VdsMax_V: 200; Value1: ? ohm; Value2: 25 nC; QgTyp_nC: 25; Vgs_V: 30; IdsMax_A: 13; SizeAreaWB_mm2: 36.5512; SizeArea_mm2: 14.9112; SizeX_mm: 6.54; SizeY_mm: 2.28; SizeZ_mm: 9.78; AEC Category: Q101
R56 R57 R76 = CRCW06033R30JNEA: RES, 3.3, 5%, 0.1 W, 0603; Manufacturer: Vishay-Dale; CompType: Resistor; Value: 3.3; Value_Code: 3R30; Tolerance_%: 5; Power_W: 0.1; Value2: 0.1W; VDC_V: 75; TempCo: 200 ppm/C; SizeArea_mm2: 1.28; SizeX_mm: 1.6; SizeY_mm: 0.8; SizeZ_mm: 1; EIA_Code: E24; U/M: EA; AEC Category: Q200
R58 R59 R64 R65 R70 R71 R77 R80 R83 = RC0603FR-075R11L: RES, 5.11, 1%, 0.1 W, 0603; Manufacturer: Yageo America; CompType: Resistor; Value: 5.11; Value_Code: 5R11; Tolerance_%: 1; Power_W: 0.1; Value2: 0.1W; VDC_V: 150; TempCo: 200 ppm/C; SizeArea_mm2: 1.28; SizeX_mm: 1.6; SizeY_mm: 0.8; EIA_Code: E96; U/M: EA; AEC Category: Q200
R60 R61 R72 R73 R78 R84 = CRCW060310R0FKEAHP: RES, 10.0, 1%, 0.25 W, 0603; Manufacturer: Vishay-Dale; CompType: Resistor; Value: 10.0; Res_ohm: 10; Value_Code: 10R0; Tolerance_%: 1; Power_W: 0.25; Value2: 0.25W; VDC_V: 75; TempCo: 100 ppm/C; SizeArea_mm2: 1.28; SizeX_mm: 1.6; SizeY_mm: 0.8; EIA_Code: E96; U/M: EA; AEC Category: Q200
R62 R63 R68 R69 R79 R82 = CRCW060351R1FKEA: RES, 51.1, 1%, 0.1 W, 0603; Manufacturer: Vishay-Dale; CompType: Resistor; Value: 51.1; Value_Code: 51R1; Tolerance_%: 1; Power_W: 0.1; Value2: 0.1W; VDC_V: 75; TempCo: 100 ppm/C; SizeArea_mm2: 1.28; SizeX_mm: 1.6; SizeY_mm: 0.8; EIA_Code: E96; U/M: EA; AEC Category: Q200
R66 R67 R74 R75 R81 R85 = CRCW060320K0FKEA: RES, 20.0 k, 1%, 0.1 W, 0603; Manufacturer: Vishay-Dale; CompType: Resistor; Value: 20.0k; Res_ohm: 20000; Value_Code: 20k0; Tolerance_%: 1; Power_W: 0.1; Value2: 0.1W; VDC_V: 75; TempCo: 100 ppm/C; SizeArea_mm2: 1.28; SizeX_mm: 1.6; SizeY_mm: 0.8; EIA_Code: E96; U/M: EA; AEC Category: Q200
R86 = PWR220T-20-R100F: RES, 0.1, 1%, 20 W, TO-220AC; Manufacturer: Bourns; CompType: Resistor; Value: 0.1; Value_Code: R100; Tolerance_%: 1; Power_W: 20; Value2: 20W; VDC_V: 250; TempCo: 100 ppm/C; EIA_Code: E96; U/M: EA; AEC Category: Q200
R87 R88 = CRCW0603100RFKEA: RES, 100, 1%, 0.1 W, 0603; Manufacturer: Vishay-Dale; CompType: Resistor; Value: 100; Value_Code: 100R; Tolerance_%: 1; Power_W: 0.1; Value2: 0.1W; VDC_V: 75; TempCo: 100 ppm/C; EIA_Code: E96; U/M: EA
SH-J12 SH-J13 SH-J15 = 969102-0000-DA: as SH-J4 on sheet TIDA-01353_System Power
TP25 TP26 TP29 TP32 TP35 TP37 = 5019: as TP5 on sheet TIDA-01353_System Power
U12-U14 = UCC27714DR: High-Speed,4A, 600V High-side Low-side Gate Driver Device, D0014A; Manufacturer: Texas Instruments; SymbolCreator: a0411947; SizeArea_mm2: 51.9; SizeAreaWB_mm2: 85.2; SizeX_mm: 6; SizeY_mm: 8.65; SizeZ_mm: 1.75; CompType: IC; U/M: EA

## Sheet TIDA-01353_MCU and Peripherals.SchDoc
size 431 x 279 mm; Date: Not shown in title block; ApprovedBy: Not shown in title block; CheckedBy: Not shown in title block; Author: Not shown in title block; CompanyName: Not shown in title block; Engineer: Not shown in title block; Organization: Not shown in title block; Address1: Not shown in title block; Address2: Not shown in title block; Address3: Not shown in title block; Address4: Not shown in title block; DocumentNumber: 1; Revision: Use project parameter SCH_Rev; SheetNumber: 3; SheetTotal: 4; PageSetup: Record=PageOptions¦CenterHorizontal=True¦CenterVertical=True¦PrintScale=1.00¦XCorrection=1.00¦YCorrection=1.00¦PrintKind=0¦BorderSize=5000000¦LeftOffset=0¦BottomOffset=0¦Orientation=2¦PaperLength=1000¦PaperWidth=1000¦Scale=100¦PaperSource=15¦PrintQuality=600¦MediaType=1¦DitherType=10¦PaperKind=Letter¦PrintScaleMode=1
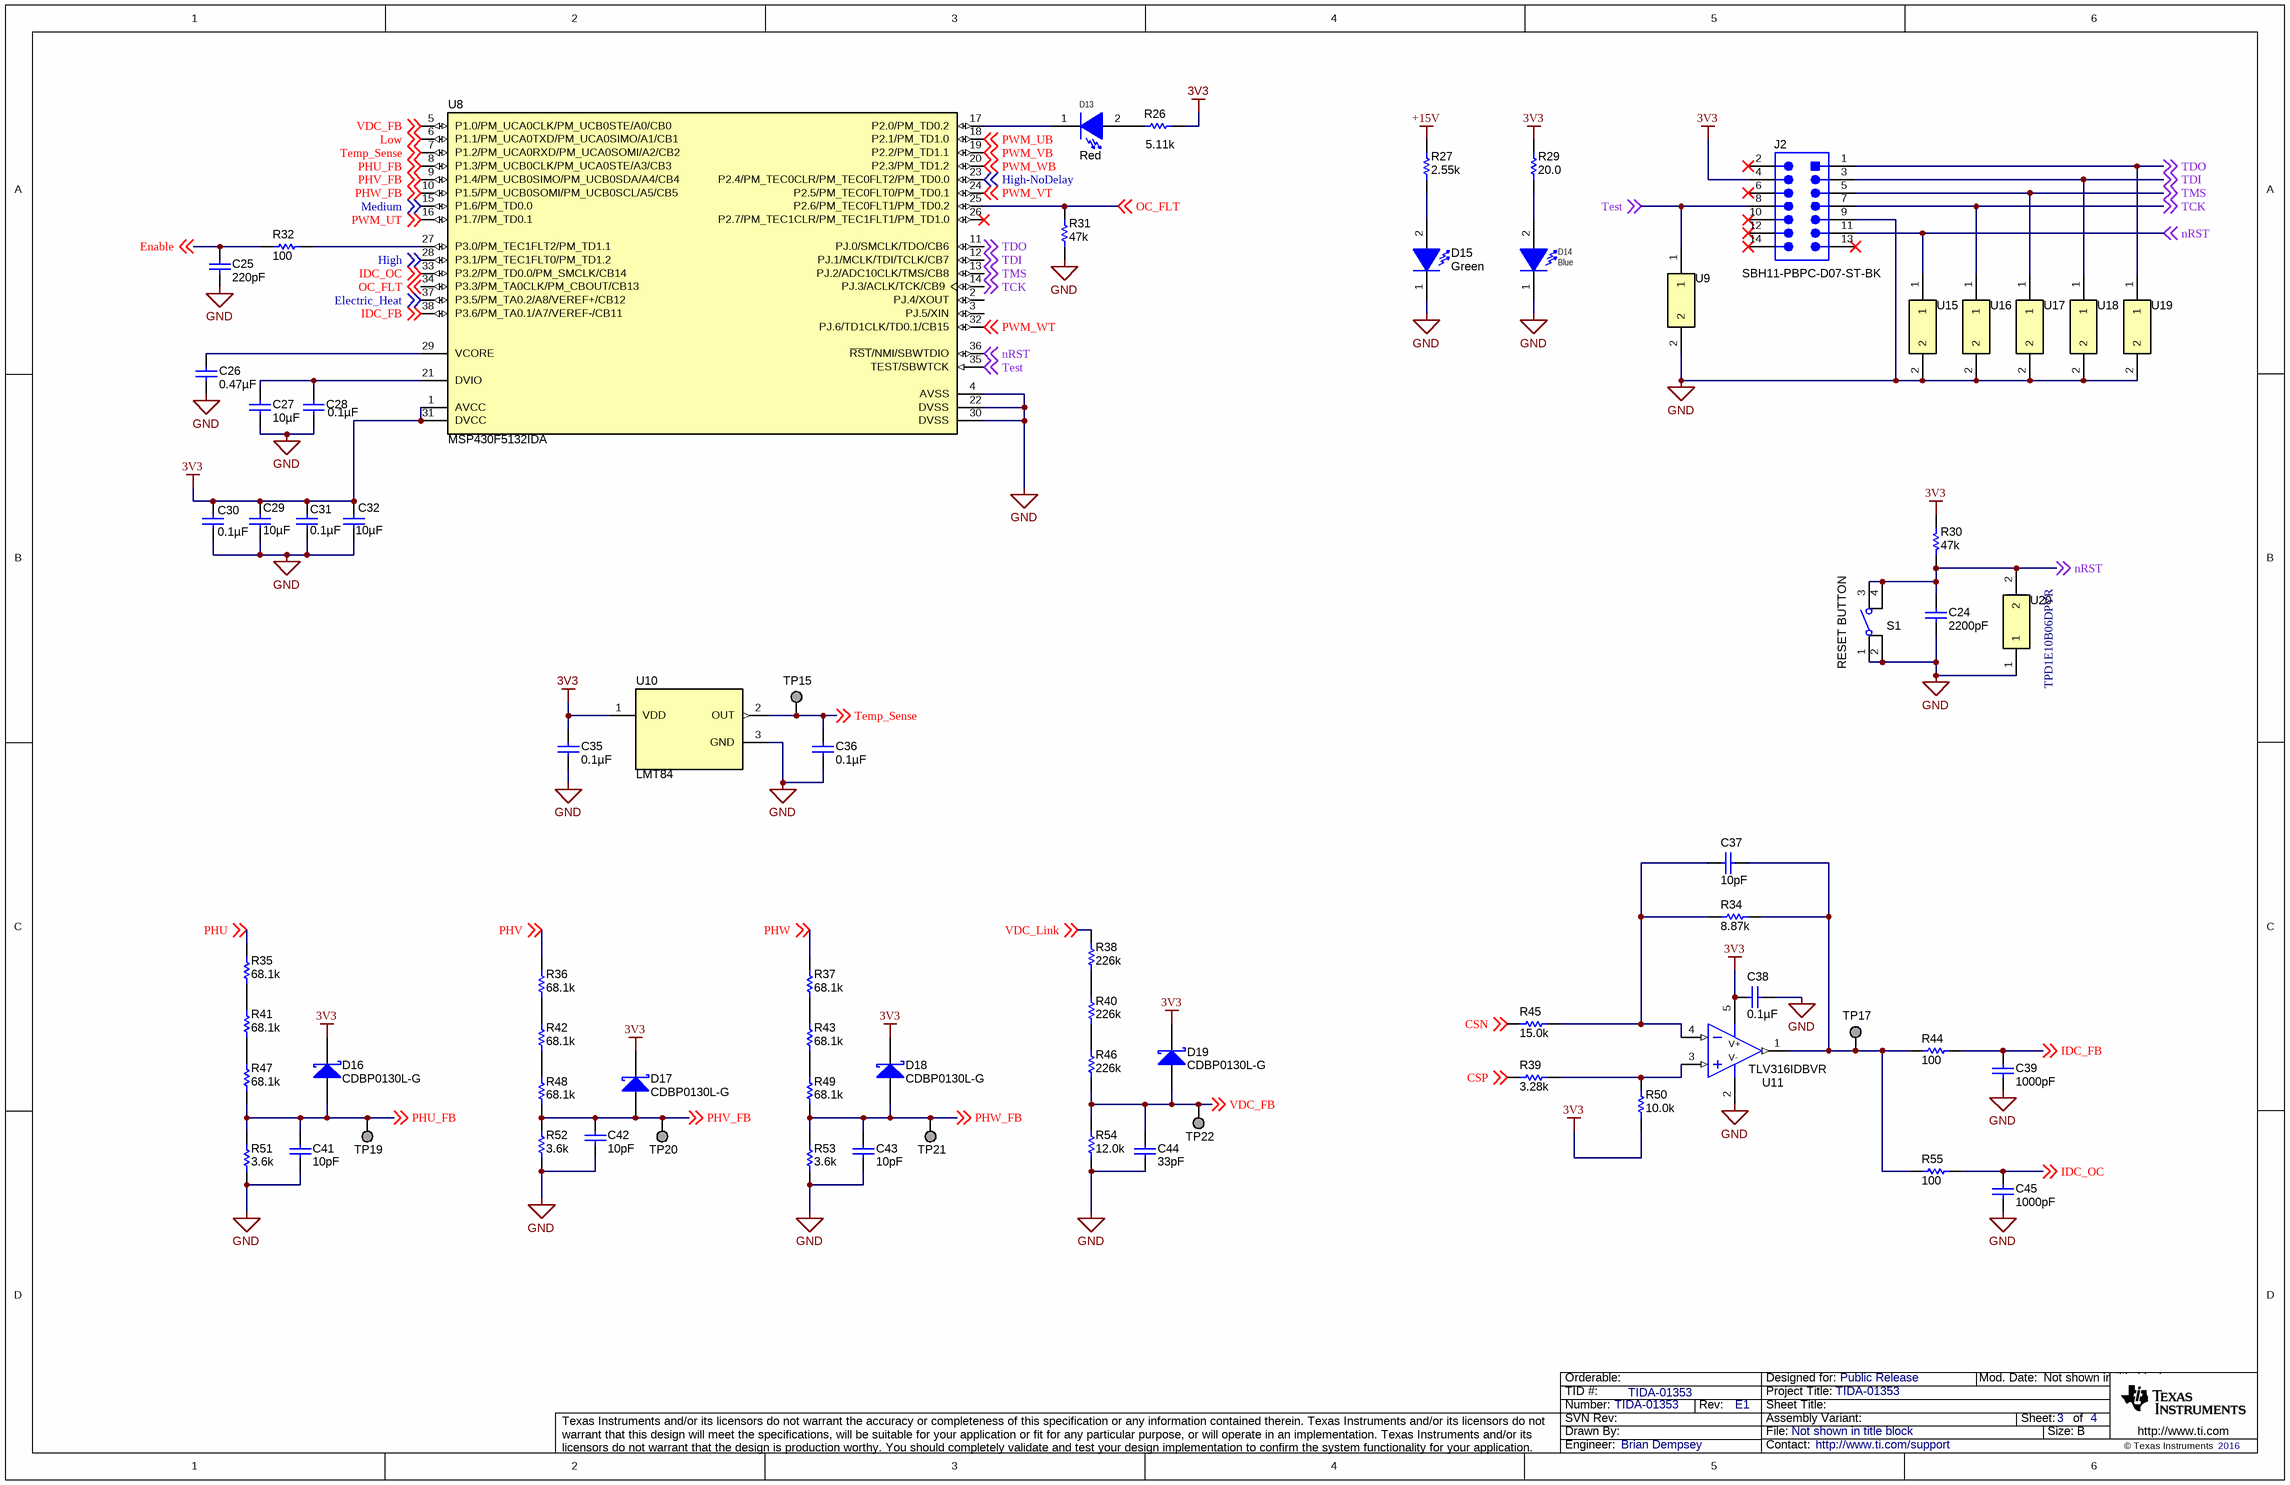
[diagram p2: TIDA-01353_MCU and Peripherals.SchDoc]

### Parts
C24  ValueDisplayed: 2200pF  [0603]  (hidden comment: C0603C222K5RAC)
C25  ValueDisplayed: 220pF  [0603]  (hidden comment: 06035A221FAT2A)
C26  ValueDisplayed: 0.47µF  [0805_HV]  (hidden comment: C0805C474K4RACTU)
C27  ValueDisplayed: 10µF  [0805_HV]  (hidden comment: 0805YD106MAT2A)
C28  ValueDisplayed: 0.1µF  [0603]  (hidden comment: 0603YC104JAT2A)
C29  ValueDisplayed: 10µF  [0805_HV]  (hidden comment: 0805YD106MAT2A)
C30  ValueDisplayed: 0.1µF  [0603]  (hidden comment: 0603YC104JAT2A)
C31  ValueDisplayed: 0.1µF  [0603]  (hidden comment: 0603YC104JAT2A)
C32  ValueDisplayed: 10µF  [0805_HV]  (hidden comment: 0805YD106MAT2A)
C35  ValueDisplayed: 0.1µF  [0603]  (hidden comment: 0603YC104JAT2A)
C36  ValueDisplayed: 0.1µF  [0603]  (hidden comment: 0603YC104JAT2A)
C37  ValueDisplayed: 10pF  [0603]  (hidden comment: 06035A100JAT2A)
C38  ValueDisplayed: 0.1µF  [0603]  (hidden comment: 0603YC104JAT2A)
C39  ValueDisplayed: 1000pF  [0603]  (hidden comment: GRM188R61H102KA01D)
C41  ValueDisplayed: 10pF  [0603]  (hidden comment: 06035A100JAT2A)
C42  ValueDisplayed: 10pF  [0603]  (hidden comment: 06035A100JAT2A)
C43  ValueDisplayed: 10pF  [0603]  (hidden comment: 06035A100JAT2A)
C44  ValueDisplayed: 33pF  [0603]  (hidden comment: 06035A330JAT2A)
C45  ValueDisplayed: 1000pF  [0603]  (hidden comment: GRM188R61H102KA01D)
D13  value Red  [WL-SMCW_RED]  (hidden comment: 150060RS75000)
D14  value Blue  [WL-SMCW_Blue]  (hidden comment: 150060BS75000)
D15  value Green  [WL-SMCW_GREEN]  (hidden comment: 150060VS75000)
D16  CDBP0130L-G  [SOD-723]
D17  CDBP0130L-G  [SOD-723]
D18  CDBP0130L-G  [SOD-723]
D19  CDBP0130L-G  [SOD-723]
J2  SBH11-PBPC-D07-ST-BK  [CONN_SBH11-PBPC-D07-ST-BK]
R26  ValueDisplayed: 5.11k  [0603]  (hidden comment: CRCW06035K11FKEA)
R27  ValueDisplayed: 2.55k  [0603]  (hidden comment: CRCW06032K55FKEA)
R29  ValueDisplayed: 20.0  [0603]  (hidden comment: CRCW060320R0FKEA)
R30  value 47k  [0603]  (hidden comment: CRCW060347K0JNEA)
R31  value 47k  [0603]  (hidden comment: CRCW060347K0JNEA)
R32  ValueDisplayed: 100  [0603]  (hidden comment: CRCW0603100RFKEA)
R34  ValueDisplayed: 8.87k  [0603]  (hidden comment: RC0603FR-078K87L)
R35  ValueDisplayed: 68.1k  [1206]  (hidden comment: CRCW120668K1FKEA)
R36  ValueDisplayed: 68.1k  [1206]  (hidden comment: CRCW120668K1FKEA)
R37  ValueDisplayed: 68.1k  [1206]  (hidden comment: CRCW120668K1FKEA)
R38  ValueDisplayed: 226k  [1206]  (hidden comment: RC1206FR-07226KL)
R39  ValueDisplayed: 3.28k  [0603]  (hidden comment: RT0603BRD073K28L)
R40  ValueDisplayed: 226k  [1206]  (hidden comment: RC1206FR-07226KL)
R41  ValueDisplayed: 68.1k  [1206]  (hidden comment: CRCW120668K1FKEA)
R42  ValueDisplayed: 68.1k  [1206]  (hidden comment: CRCW120668K1FKEA)
R43  ValueDisplayed: 68.1k  [1206]  (hidden comment: CRCW120668K1FKEA)
R44  ValueDisplayed: 100  [0603]  (hidden comment: CRCW0603100RFKEA)
R45  ValueDisplayed: 15.0k  [0603]  (hidden comment: CRCW060315K0FKEA)
R46  ValueDisplayed: 226k  [1206]  (hidden comment: RC1206FR-07226KL)
R47  ValueDisplayed: 68.1k  [1206]  (hidden comment: CRCW120668K1FKEA)
R48  ValueDisplayed: 68.1k  [1206]  (hidden comment: CRCW120668K1FKEA)
R49  ValueDisplayed: 68.1k  [1206]  (hidden comment: CRCW120668K1FKEA)
R50  ValueDisplayed: 10.0k  [0603]  (hidden comment: RG1608P-103-B-T5)
R51  ValueDisplayed: 3.6k  [0603]  (hidden comment: CRCW06033K60JNEA)
R52  ValueDisplayed: 3.6k  [0603]  (hidden comment: CRCW06033K60JNEA)
R53  ValueDisplayed: 3.6k  [0603]  (hidden comment: CRCW06033K60JNEA)
R54  ValueDisplayed: 12.0k  [0603]  (hidden comment: RC0603FR-0712KL)
R55  ValueDisplayed: 100  [0603]  (hidden comment: CRCW0603100RFKEA)
S1  4-1437565-1  [SW_FSM4JSMA]  (value not drawn)
TP15  TESTPOINT  [Keystone_5019]  (value not drawn)  (no BOM)
TP17  TESTPOINT  [Keystone_5019]  (value not drawn)  (no BOM)
TP19  TESTPOINT  [Keystone_5019]  (value not drawn)  (no BOM)
TP20  TESTPOINT  [Keystone_5019]  (value not drawn)  (no BOM)
TP21  TESTPOINT  [Keystone_5019]  (value not drawn)  (no BOM)
TP22  TESTPOINT  [Keystone_5019]  (value not drawn)  (no BOM)
U8  MSP430F5132IDA  [DA0038A_N]
U9  TPD1E10B06DPYR  [DPY0002A]  (value not drawn)
U10  LMT84  [LP0003A_straight]
U11  TLV316IDBVR  [DBV0005A_N]
U15  TPD1E10B06DPYR  [DPY0002A]  (value not drawn)
U16  TPD1E10B06DPYR  [DPY0002A]  (value not drawn)
U17  TPD1E10B06DPYR  [DPY0002A]  (value not drawn)
U18  TPD1E10B06DPYR  [DPY0002A]  (value not drawn)
U19  TPD1E10B06DPYR  [DPY0002A]  (value not drawn)
U20  TPD1E10B06DPYR  [DPY0002A]

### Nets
3V3: C29.1 C30.1 C31.1 C32.1 C35.2 C38.1 D16.1(K) D17.1(K) D18.1(K) D19.1(K) J2.4 R26.1 R29.2 R30.2 R50.1 U8.1(AVCC) U8.31(DVCC) U10.1(VDD) U11.5(V+)
+15V: R27.1
GND: C24.2 C25.2 C26.2 C27.2 C28.2 C29.2 C30.2 C31.2 C32.2 C35.1 C36.1 C38.2 C39.1 C41.2 C42.2 C43.2 C44.2 C45.1 D14.1(K) D15.1(K) J2.9 R31.1 R51.1 R52.1 R53.1 R54.1 S1.1 S1.2 U8.4(AVSS) U8.22(DVSS) U8.30(DVSS) U9.2 U10.3(GND) U11.2(V-) U15.2 U16.2 U17.2 U18.2 U19.2 U20.1
CSN: R45.1 ; off-sheet CSN
CSP: R39.1 ; off-sheet CSP
Electric_Heat: U8.37(P3.5/PM_TA0.2/A8/VEREF+/CB12) ; off-sheet Electric_Heat
Enable: C25.1 R32.2 ; off-sheet Enable
High: U8.28(P3.1/PM_TEC1FLT0/PM_TD1.2) ; off-sheet High
High-NoDelay: U8.23(P2.4/PM_TEC0CLR/PM_TEC0FLT2/PM_TD0.0) ; off-sheet High-NoDelay
IDC_FB: C39.2 R44.1 U8.38(P3.6/PM_TA0.1/A7/VEREF-/CB11) ; off-sheet IDC_FB
IDC_OC: C45.2 R55.1 U8.33(P3.2/PM_TD0.0/PM_SMCLK/CB14) ; off-sheet IDC_OC
Low: U8.6(P1.1/PM_UCA0TXD/PM_UCA0SIMO/A1/CB1) ; off-sheet Low
Medium: U8.15(P1.6/PM_TD0.0) ; off-sheet Medium
nRST: C24.1 J2.11 R30.1 S1.3 S1.4 U8.36(~{RST}/NMI/SBWTDIO) U15.1 U20.2 ; off-sheet nRST
OC_FLT: R31.2 U8.25(P2.6/PM_TEC0FLT1/PM_TD0.2) U8.34(P3.3/PM_TA0CLK/PM_CBOUT/CB13) ; off-sheet OC_FLT
PHU: R35.2 ; off-sheet PHU
PHU_FB: C41.1 D16.2(A) R47.1 R51.2 TP19.1 U8.8(P1.3/PM_UCB0CLK/PM_UCA0STE/A3/CB3) ; off-sheet PHU_FB
PHV: R36.2 ; off-sheet PHV
PHV_FB: C42.1 D17.2(A) R48.1 R52.2 TP20.1 U8.9(P1.4/PM_UCB0SIMO/PM_UCB0SDA/A4/CB4) ; off-sheet PHV_FB
PHW: R37.2 ; off-sheet PHW
PHW_FB: C43.1 D18.2(A) R49.1 R53.2 TP21.1 U8.10(P1.5/PM_UCB0SOMI/PM_UCB0SCL/A5/CB5) ; off-sheet PHW_FB
PWM_UB: U8.18(P2.1/PM_TD1.0) ; off-sheet PWM_UB
PWM_UT: U8.16(P1.7/PM_TD0.1) ; off-sheet PWM_UT
PWM_VB: U8.19(P2.2/PM_TD1.1) ; off-sheet PWM_VB
PWM_VT: U8.24(P2.5/PM_TEC0FLT0/PM_TD0.1) ; off-sheet PWM_VT
PWM_WB: U8.20(P2.3/PM_TD1.2) ; off-sheet PWM_WB
PWM_WT: U8.32(PJ.6/TD1CLK/TD0.1/CB15) ; off-sheet PWM_WT
TCK: J2.7 U8.14(PJ.3/ACLK/TCK/CB9) U16.1 ; off-sheet TCK
TDI: J2.3 U8.12(PJ.1/MCLK/TDI/TCLK/CB7) U18.1 ; off-sheet TDI
TDO: J2.1 U8.11(PJ.0/SMCLK/TDO/CB6) U19.1 ; off-sheet TDO
Temp_Sense: C36.2 TP15.1 U8.7(P1.2/PM_UCA0RXD/PM_UCA0SOMI/A2/CB2) U10.2(OUT) ; off-sheet Temp_Sense
Test: J2.8 U8.35(TEST/SBWTCK) U9.1 ; off-sheet Test
TMS: J2.5 U8.13(PJ.2/ADC10CLK/TMS/CB8) U17.1 ; off-sheet TMS
VDC_FB: C44.1 D19.2(A) R46.1 R54.2 TP22.1 U8.5(P1.0/PM_UCA0CLK/PM_UCB0STE/A0/CB0) ; off-sheet VDC_FB
VDC_Link: R38.2 ; off-sheet VDC_Link
NetC26_1: C26.1 U8.29(VCORE)
NetC27_1: C27.1 C28.1 U8.21(DVIO)
NetC37_1: C37.1 R34.1 R44.2 R55.2 TP17.1 U11.1(OUT)
NetC37_2: C37.2 R34.2 R45.2 U11.4(IN-)
NetD13_1: D13.1(K) U8.17(P2.0/PM_TD0.2)
NetD13_2: D13.2(A) R26.2
NetD14_2: D14.2(A) R29.1
NetD15_2: D15.2(A) R27.2
NetR32_1: R32.1 U8.27(P3.0/PM_TEC1FLT2/PM_TD1.1)
NetR35_1: R35.1 R41.2
NetR36_1: R36.1 R42.2
NetR37_1: R37.1 R43.2
NetR38_1: R38.1 R40.2
NetR39_2: R39.2 R50.2 U11.3(IN+)
NetR40_1: R40.1 R46.2
NetR41_1: R41.1 R47.2
NetR42_1: R42.1 R48.2
NetR43_1: R43.1 R49.2

Not connected (* = marked no-connect by the designer): J2 2* 6* 10* 12* 13* 14*; U8 2(PJ.4/XOUT) 3(PJ.5/XIN) 26(P2.7/PM_TEC1CLR/PM_TEC1FLT1/PM_TD1.0)*

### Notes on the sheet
- (near S1) RESET BUTTON

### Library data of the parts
C24 = C0603C222K5RAC: CAP, CERM, 2200 pF, 50 V, +/- 10%, X7R, 0603; Manufacturer: Kemet; Polarized: N; CompType: Capacitor; Value: 2200pF; U/M: EA; Cap_F: 0.0000000022; Tolerance_%: 10; Value1: Unknown; VDC_V: 50; Value2: 50V; TaMin_C: -55; TaMax_C: 125
C25 = 06035A221FAT2A: CAP, CERM, 220 pF, 50 V, +/- 1%, C0G/NP0, 0603; Manufacturer: AVX; Polarized: N; CompType: Capacitor; Value: 220pF; U/M: EA; Cap_F: 0.00000000022; Tolerance_%: 1; ESR_ohm: 0.083; Value1: 0.083 ohm; VDC_V: 50; Value2: 50V; TaMin_C: -55; TaMax_C: 125
C26 = C0805C474K4RACTU: CAP, CERM, 0.47 µF, 16 V, +/- 10%, X7R, 0805; Manufacturer: Kemet; Polarized: N; CompType: Capacitor; Value: 0.47uF; U/M: EA; Cap_F: 0.00000047; Tolerance_%: 10; Value1: Unknown; VDC_V: 16; Value2: 16V; TaMin_C: -55; TaMax_C: 125; Cap_Case: 0805
C27 C29 C32 = 0805YD106MAT2A: CAP, CERM, 10uF, 16V, +/-20%, X5R, 0805; Manufacturer: AVX; Polarized: N; CompType: Capacitor; U/M: EA; Cap_F: 0.00001; Tolerance_%: 20; Value1: Unknown; VDC_V: 16; TaMin_C: -55; TaMax_C: 85; Cap_Case: 0805
C28 C30 C31 = 0603YC104JAT2A: CAP, CERM, 0.1 µF, 16 V, +/- 5%, X7R, 0603; Manufacturer: AVX; Polarized: N; CompType: Capacitor; Value: 0.1uF; U/M: EA; Cap_F: 0.0000001; Tolerance_%: 5; ESR_ohm: 0.039; Value1: 0.039 ohm; VDC_V: 16; Value2: 16V; TaMin_C: -55; TaMax_C: 125
C35 C36 = 0603YC104JAT2A: CAP, CERM, 0.1 µF, 16 V, +/- 5%, X7R, 0603; Manufacturer: AVX; Polarized: N; CompType: Capacitor; Value: 0.1uF; U/M: EA; Cap_F: 0.0000001; Tolerance_%: 5; ESR_ohm: 0.039; Value1: 0.039 ohm; VDC_V: 16; Value2: 16V; TaMin_C: -55; TaMax_C: 125; SizeArea_mm2: 1.28; SizeAreaWB_mm2: 4.68; SizeX_mm: 1.6; SizeY_mm: 0.8; SizeZ_mm: 1; AEC Category: Q200
C37 C41-C43 = 06035A100JAT2A: CAP, CERM, 10 pF, 50 V, +/- 5%, C0G/NP0, 0603; Manufacturer: AVX; Polarized: N; CompType: Capacitor; Value: 10pF; U/M: EA; Cap_F: 0.00000000001; Tolerance_%: 5; ESR_ohm: 0.403; Value1: 0.403 ohm; VDC_V: 50; Value2: 50V; TaMin_C: -55; TaMax_C: 125
C38 = 0603YC104JAT2A: CAP, CERM, 0.1uF, 16V, +/-5%, X7R, 0603; Manufacturer: AVX; Polarized: N; CompType: Capacitor; U/M: EA; Cap_F: 0.0000001; Tolerance_%: 5; ESR_Ohm: 0.039; Value1: 0.039 ohm; VDC_V: 16; TaMin_C: -55; TaMax_C: 125
C39 C45 = GRM188R61H102KA01D: as C67 on sheet TIDA-01353_Motor Control
C44 = 06035A330JAT2A: CAP, CERM, 33 pF, 50 V, +/- 5%, C0G/NP0, 0603; Manufacturer: AVX; Polarized: N; CompType: Capacitor; Value: 33pF; U/M: EA; Cap_F: 0.000000000033; Tolerance_%: 5; ESR_ohm: 0.209; Value1: 0.209 ohm; VDC_V: 50; Value2: 50V; TaMin_C: -55; TaMax_C: 125
D13 = 150060RS75000: LED, Red, SMD; Manufacturer: Wurth Elektronik; Type: AlInGaP; Vf_V: 2; Value2: 2V; Io_A: 0.03; Vr_V: 5; Tjmax_C: 85; Power_TotalModule: 0.072; Value1: 0.072W; Angle: 140; U/M: EA
D14 = 150060BS75000: LED, Blue, SMD; Manufacturer: Wurth Elektronik; Type: InGaN; Vf_V: 3.2; Value2: 3.2V; Io_A: 0.03; Vr_V: 5; Tjmax_C: 85; Power_TotalModule: 0.105; Value1: 0.105W; Angle: 140; U/M: EA
D15 = 150060VS75000: LED, Green, SMD; Manufacturer: Wurth Elektronik; Type: AlInGaP; Vf_V: 2; Value2: 2V; Io_A: 0.02; Value1: W; U/M: EA
D16-D19 = CDBP0130L-G: Diode, Schottky, 30 V, 0.1 A, SOD-723; Manufacturer: Comchip Technology; U/M: EA; Vf_V: 0.35; Value: 30V; Value1: 0.1A; Value2: 0.35V; Io_A: 0.1; Vr_V: 30; TJmax_C: 125
J2 = SBH11-PBPC-D07-ST-BK: Header (shrouded), 100 mil, 7x2, Gold, TH; Manufacturer: Sullins Connector Solutions; SymbolCreator: a0412235
R26 = CRCW06035K11FKEA: RES, 5.11 k, 1%, 0.1 W, 0603; Manufacturer: Vishay-Dale; CompType: Resistor; Value: 5.11k; Res_ohm: 5110; Value_Code: 5k11; Tolerance_%: 1; Power_W: 0.1; Value2: 0.1W; VDC_V: 75; TempCo: 100 ppm/C; EIA_Code: E96; U/M: EA; SizeArea_mm2: 1.28; SizeX_mm: 1.6; SizeY_mm: 0.8; AEC Category: Q200
R27 = CRCW06032K55FKEA: RES, 2.55 k, 1%, 0.1 W, 0603; Manufacturer: Vishay-Dale; CompType: Resistor; Value: 2.55k; Res_ohm: 2550; Value_Code: 2k55; Tolerance_%: 1; Power_W: 0.1; Value2: 0.1W; VDC_V: 75; TempCo: 100 ppm/C; EIA_Code: E96; U/M: EA; SizeArea_mm2: 1.28; SizeX_mm: 1.6; SizeY_mm: 0.8; AEC Category: Q200
R29 = CRCW060320R0FKEA: RES, 20.0, 1%, 0.1 W, 0603; Manufacturer: Vishay-Dale; CompType: Resistor; Value: 20.0; Res_ohm: 20; Value_Code: 20R0; Tolerance_%: 1; Power_W: 0.1; Value2: 0.1W; VDC_V: 75; TempCo: 100 ppm/C; EIA_Code: E96; U/M: EA; SizeArea_mm2: 1.28; SizeX_mm: 1.6; SizeY_mm: 0.8; AEC Category: Q200
R30 R31 = CRCW060347K0JNEA: as R1 on sheet TIDA-01353_System Power
R32 R44 R55 = CRCW0603100RFKEA: as R87 on sheet TIDA-01353_Motor Control
R34 = RC0603FR-078K87L: RES, 8.87 k, 1%, 0.1 W, 0603; Manufacturer: Yageo America; CompType: Resistor; Value: 8.87k; Res_ohm: 8870; Value_Code: 8k87; Tolerance_%: 1; Power_W: 0.1; Value2: 0.1W; VDC_V: 150; TempCo: 200 ppm/C; EIA_Code: E96; U/M: EA; SizeArea_mm2: 1.28; SizeX_mm: 1.6; SizeY_mm: 0.8; AEC Category: Q200
R35-R37 R41-R43 R47-R49 = CRCW120668K1FKEA: RES, 68.1 k, 1%, 0.25 W, 1206; Manufacturer: Vishay-Dale; CompType: Resistor; Value: 68.1k; Res_ohm: 68100; Value_Code: 68k1; Tolerance_%: 1; Power_W: 0.25; Value2: 0.25W; VDC_V: 200; TempCo: 100 ppm/C; EIA_Code: E96; U/M: EA; SizeArea_mm2: 5.12; SizeX_mm: 3.2; SizeY_mm: 1.6; SizeZ_mm: 1.35; AEC Category: Q200
R38 R40 R46 = RC1206FR-07226KL: RES, 226 k, 1%, 0.25 W, 1206; Manufacturer: Yageo America; CompType: Resistor; Value: 226k; Res_ohm: 226000; Tolerance_%: 1; Power_W: 0.25; Value2: 0.25W; VDC_V: 200; TempCo: 100 ppm/C; EIA_Code: E96; U/M: EA; SizeArea_mm2: 5.12; SizeX_mm: 3.2; SizeY_mm: 1.6; SizeZ_mm: 1.35; AEC Category: Q200
R39 = RT0603BRD073K28L: RES, 3.28 k, 0.1%, 0.1 W, 0603; Manufacturer: Yageo America; CompType: Resistor; Value: 3.28k; Res_ohm: 3280; Value_Code: 3k28; Tolerance_%: 0.1; Value2: 0.1W; VDC_V: 75; TempCo: 25 ppm/C; EIA_Code: E192; U/M: EA; SizeArea_mm2: 1.28; SizeX_mm: 1.6; SizeY_mm: 0.8; SizeZ_mm: 1; AEC Category: Q200
R45 = CRCW060315K0FKEA: RES, 15.0 k, 1%, 0.1 W, 0603; Manufacturer: Vishay-Dale; CompType: Resistor; Value: 15.0k; Res_ohm: 15000; Value_Code: 15k0; Tolerance_%: 1; Power_W: 0.1; Value2: 0.1W; VDC_V: 75; TempCo: 100 ppm/C; EIA_Code: E96; U/M: EA; SizeArea_mm2: 1.28; SizeX_mm: 1.6; SizeY_mm: 0.8; AEC Category: Q200
R50 = RG1608P-103-B-T5: RES, 10.0 k, 0.1%, 0.1 W, 0603; Manufacturer: Susumu Co Ltd; CompType: Resistor; Value: 10.0k; Res_ohm: 10000; Value_Code: 10k0; Tolerance_%: 0.1; Value2: 0.1W; VDC_V: 75; TempCo: 25 ppm/C; EIA_Code: E192; U/M: EA; SizeArea_mm2: 1.28; SizeX_mm: 1.6; SizeY_mm: 0.8; SizeZ_mm: 1; AEC Category: Q200
R51-R53 = CRCW06033K60JNEA: RES, 3.6 k, 5%, 0.1 W, 0603; Manufacturer: Vishay-Dale; CompType: Resistor; Value: 3.6k; Res_ohm: 3600; Value_Code: 3k60; Tolerance_%: 5; Power_W: 0.1; Value2: 0.1W; VDC_V: 75; TempCo: 200 ppm/C; EIA_Code: E24; U/M: EA
R54 = RC0603FR-0712KL: RES, 12.0 k, 1%, 0.1 W, 0603; Manufacturer: Yageo America; CompType: Resistor; Value: 12.0k; Res_ohm: 12000; Value_Code: 12k0; Tolerance_%: 1; Power_W: 0.1; Value2: 0.1W; VDC_V: 150; TempCo: 200 ppm/C; U/M: EA
S1 = 4-1437565-1: Switch, Tactile, SPST-NO, 0.05A, 12V, SMT; Manufacturer: TE Connectivity; SymbolCreator: a0412235; VDC_V: 12; SwitchFunction: Off-Mom; PositionCount: 1; CurrentRating_mA: 50
TP15 TP17 TP19-TP22 = 5019: as TP5 on sheet TIDA-01353_System Power
U8 = MSP430F5132IDA: 25 MHz Mixed Signal Microcontroller with 8 KB Flash, 1024 B SRAM and 29 GPIOs, -40 to 85 degC, 38-pin SOP (DA), Green (RoHS & no Sb/Br); Alternate Manufacturer: Texas Instruments; Alternate PartNumber: Equivalent; ADC: 10-bit SAR; ADC Channels: 8; Brown Out Reset: Yes; DMA: 3; Frequency(MHz): 25; GPIO: 29; Multiplier: 32x32; Pin/Package: 38TSSOP, 40WQFN; SRAM(B): 1024; SubFamily: 5 Series; USCI_A (UART/LIN/IrDA/SPI): 1
U9 U15-U20 = TPD1E10B06DPYR: ESD in 0402 Package with 10 pF Capacitance and 6 V Breakdown, 1 Channel, -40 to +125 degC, 2-pin X2SON (DPY), Green (RoHS & no Sb/Br); Manufacturer: Texas Instruments; Alternate PartNumber: Equivalent; Breakdown Voltage(Min)(V): 6; Eco-Plan: TBD; IEC 61000-4-2 Air-Gap(+/- kV): 30; IO Capacitance(Typ)(pF): 10; SubFamily: ESD Solution
U10 = LMT84LPM: 1.5V, TO-92, Analog Temperature Sensor with Class-AB Output, LP0003A; Manufacturer: Texas Instruments; SymbolCreator: a0411947; SizeArea_mm2: 18.4; SizeAreaWB_mm2: 39.76; SizeX_mm: 3.68; SizeY_mm: 5; SizeZ_mm: 9.33; CompType: IC; U/M: EA
U11 = TLV316IDBVR: 10-MHz, Rail-to-Rail Input/Output, Low-Voltage, 1.8-V CMOS Operational Amplifier, DBV0005A (SOT-5); Alternate PartNumber: TLV316IDBVT; Manufacturer: Texas Instruments; SizeArea_mm2: 8.12; SizeAreaWB_mm2: 14.82; SizeX_mm: 2.8; SizeY_mm: 2.9; SizeZ_mm: 1.45; CompType: IC; U/M: EA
